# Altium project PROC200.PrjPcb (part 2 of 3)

## Sheet PROC200_MII0_PHY2.SchDoc
size 431 x 279 mm; SheetNumber: 11; SheetTotal: 18
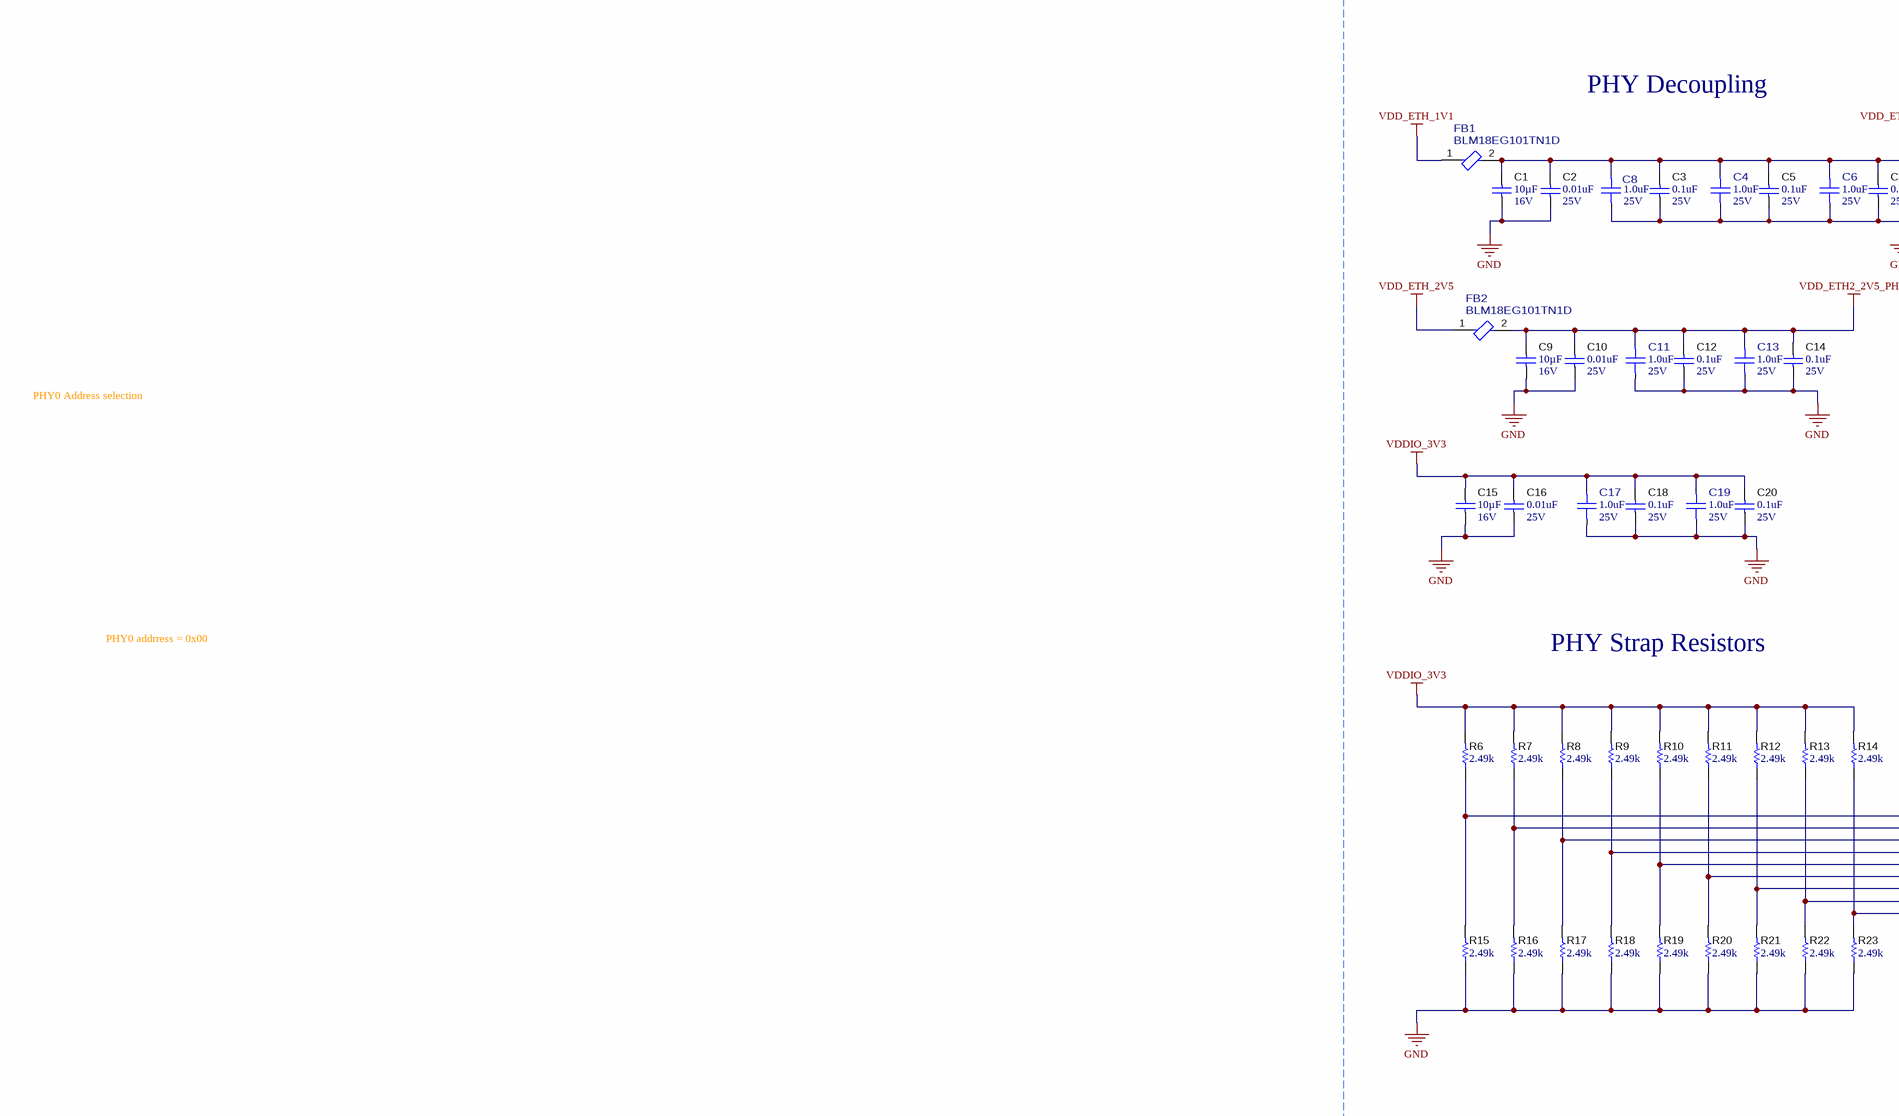
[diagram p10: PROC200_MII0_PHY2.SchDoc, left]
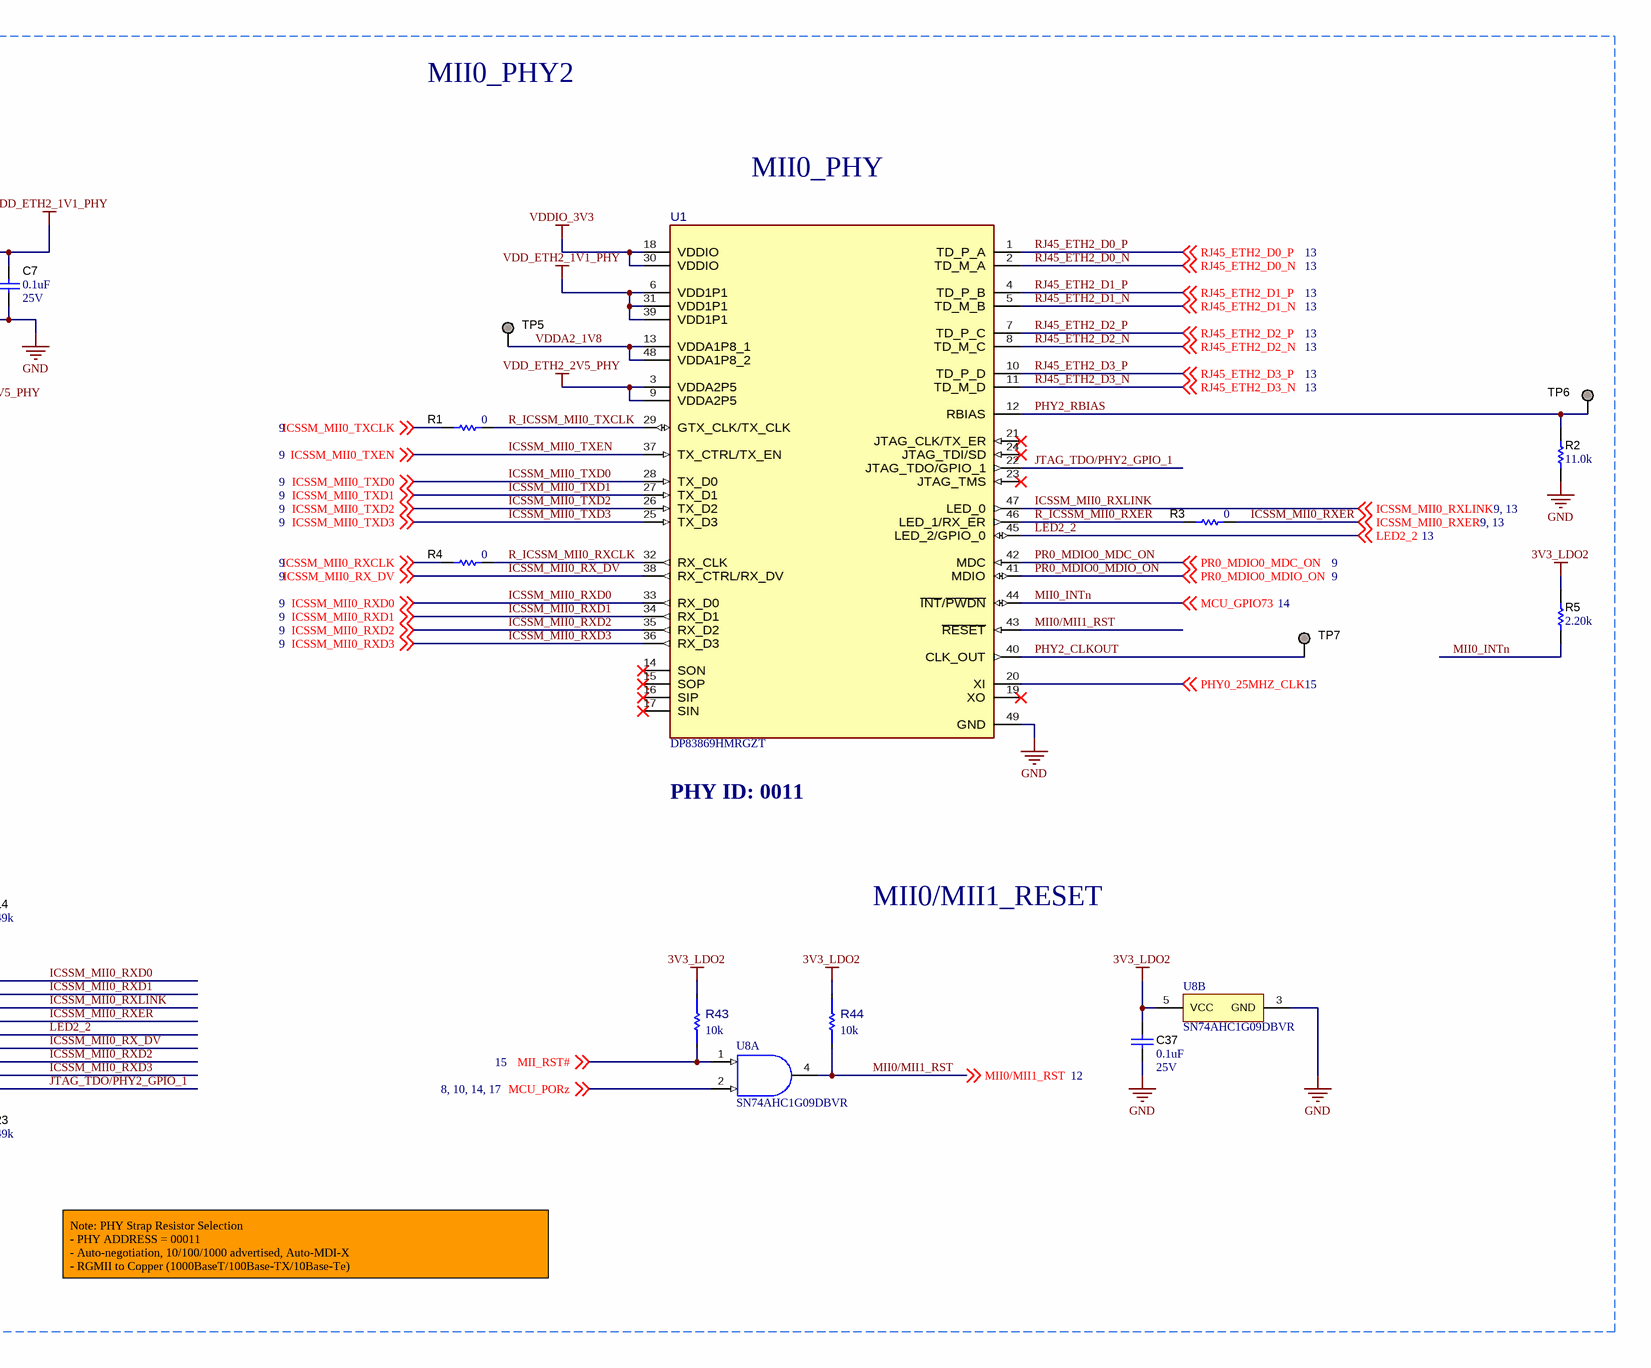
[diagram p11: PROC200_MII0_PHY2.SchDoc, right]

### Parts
C1  VDC_V: 16V  ValueDisplayed: 10µF  [0603]  (hidden comment: GRM188C81C106MA73D)
C2  Value2: 25V  ValueDisplayed: 0.01uF  [0402]  (hidden comment: GCM155R71E103KA37D)
C3  VDC_V: 25V  ValueDisplayed: 0.1uF  [0402]  (hidden comment: GRM155R71E104KE14D)
C4  ValueDisplayed: 1.0uF  VDC_V: 25V  [FP-GRM155C81E105KE11D_0402-MFG]  (hidden comment: GRM155C81E105KE11D)
C5  VDC_V: 25V  ValueDisplayed: 0.1uF  [0402]  (hidden comment: GRM155R71E104KE14D)
C6  ValueDisplayed: 1.0uF  VDC_V: 25V  [FP-GRM155C81E105KE11D_0402-MFG]  (hidden comment: GRM155C81E105KE11D)
C7  VDC_V: 25V  ValueDisplayed: 0.1uF  [0402]  (hidden comment: GRM155R71E104KE14D)
C8  ValueDisplayed: 1.0uF  VDC_V: 25V  [FP-GRM155C81E105KE11D_0402-MFG]  (hidden comment: GRM155C81E105KE11D)
C9  VDC_V: 16V  ValueDisplayed: 10µF  [0603]  (hidden comment: GRM188C81C106MA73D)
C10  Value2: 25V  ValueDisplayed: 0.01uF  [0402]  (hidden comment: GCM155R71E103KA37D)
C11  ValueDisplayed: 1.0uF  VDC_V: 25V  [FP-GRM155C81E105KE11D_0402-MFG]  (hidden comment: GRM155C81E105KE11D)
C12  VDC_V: 25V  ValueDisplayed: 0.1uF  [0402]  (hidden comment: GRM155R71E104KE14D)
C13  ValueDisplayed: 1.0uF  VDC_V: 25V  [FP-GRM155C81E105KE11D_0402-MFG]  (hidden comment: GRM155C81E105KE11D)
C14  VDC_V: 25V  ValueDisplayed: 0.1uF  [0402]  (hidden comment: GRM155R71E104KE14D)
C15  VDC_V: 16V  ValueDisplayed: 10µF  [0603]  (hidden comment: GRM188C81C106MA73D)
C16  Value2: 25V  ValueDisplayed: 0.01uF  [0402]  (hidden comment: GCM155R71E103KA37D)
C17  ValueDisplayed: 1.0uF  VDC_V: 25V  [FP-GRM155C81E105KE11D_0402-MFG]  (hidden comment: GRM155C81E105KE11D)
C18  VDC_V: 25V  ValueDisplayed: 0.1uF  [0402]  (hidden comment: GRM155R71E104KE14D)
C19  ValueDisplayed: 1.0uF  VDC_V: 25V  [FP-GRM155C81E105KE11D_0402-MFG]  (hidden comment: GRM155C81E105KE11D)
C20  VDC_V: 25V  ValueDisplayed: 0.1uF  [0402]  (hidden comment: GRM155R71E104KE14D)
C37  Value2: 25V  ValueDisplayed: 0.1uF  [0402]  (hidden comment: GRM155R71E104KE14D)
FB1  BLM18EG101TN1D  [FP-BLM18EG101TN1D_0603-MFG]
FB2  BLM18EG101TN1D  [FP-BLM18EG101TN1D_0603-MFG]
R1  ValueDisplayed: 0  [0402]  (hidden comment: ERJ-2GE0R00X)
R2  ValueDisplayed: 11.0k  [0402]  (hidden comment: CRCW040211K0FKED)
R3  ValueDisplayed: 0  [0402]  (hidden comment: ERJ-2GE0R00X)
R4  ValueDisplayed: 0  [0402]  (hidden comment: ERJ-2GE0R00X)
R5  ValueDisplayed: 2.20k  [0402]  (hidden comment: CRCW04022K20FKED)
R6  ValueDisplayed: 2.49k  [0402]  (hidden comment: CRCW04022K49FKED)
R7  ValueDisplayed: 2.49k  [0402]  (hidden comment: CRCW04022K49FKED)
R8  ValueDisplayed: 2.49k  [0402]  (hidden comment: CRCW04022K49FKED)
R9  ValueDisplayed: 2.49k  [0402]  (hidden comment: CRCW04022K49FKED)
R10  ValueDisplayed: 2.49k  [0402]  (hidden comment: CRCW04022K49FKED)
R11  ValueDisplayed: 2.49k  [0402]  (hidden comment: CRCW04022K49FKED)
R12  ValueDisplayed: 2.49k  [0402]  (hidden comment: CRCW04022K49FKED)
R13  ValueDisplayed: 2.49k  [0402]  (hidden comment: CRCW04022K49FKED)
R14  ValueDisplayed: 2.49k  [0402]  (hidden comment: CRCW04022K49FKED)
R15  ValueDisplayed: 2.49k  [0402]  (hidden comment: CRCW04022K49FKED)
R16  ValueDisplayed: 2.49k  [0402]  (hidden comment: CRCW04022K49FKED)
R17  ValueDisplayed: 2.49k  [0402]  (hidden comment: CRCW04022K49FKED)
R18  ValueDisplayed: 2.49k  [0402]  (hidden comment: CRCW04022K49FKED)
R19  ValueDisplayed: 2.49k  [0402]  (hidden comment: CRCW04022K49FKED)
R20  ValueDisplayed: 2.49k  [0402]  (hidden comment: CRCW04022K49FKED)
R21  ValueDisplayed: 2.49k  [0402]  (hidden comment: CRCW04022K49FKED)
R22  ValueDisplayed: 2.49k  [0402]  (hidden comment: CRCW04022K49FKED)
R23  ValueDisplayed: 2.49k  [0402]  (hidden comment: CRCW04022K49FKED)
R43  value 10k  [FP-RC0402JR-0710KL_0402-MFG]  (hidden comment: RC0402JR-0710KL)
R44  value 10k  [FP-RC0402JR-0710KL_0402-MFG]  (hidden comment: RC0402JR-0710KL)
TP5  TESTPOINT  [TP_25MIL-SMT]  (value not drawn)  (no BOM)
TP6  TESTPOINT  [TP_25MIL-SMT]  (value not drawn)  (no BOM)
TP7  TESTPOINT  [TP_25MIL-SMT]  (value not drawn)  (no BOM)
U1  DP83869HMRGZT  [RGZ0048B-MFG]
U8  SN74AHC1G09DBVR  [DBV0005A_N]  (parts A,B of 2)

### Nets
3V3_LDO2: C37.2 R5.2 R43.1 R44.1 U8.5(VCC)
GND: C1.1 C2.2 C3.2 C4.2 C5.2 C6.2 C7.2 C8.2 C9.1 C10.2 C11.2 C12.2 C13.2 C14.2 C15.1 C16.2 C17.2 C18.2 C19.2 C20.2 C37.1 R2.2 R15.1 R16.1 R17.1 R18.1 R19.1 R20.1 R21.1 R22.1 R23.1 U1.49(GND) U8.3(GND)
VDD_ETH2_1V1_PHY: C1.2 C2.1 C3.1 C4.1 C5.1 C6.1 C7.1 C8.1 FB1.2 U1.6(VDD1P1) U1.31(VDD1P1) U1.39(VDD1P1)
VDD_ETH2_2V5_PHY: C9.2 C10.1 C11.1 C12.1 C13.1 C14.1 FB2.2 U1.3(VDDA2P5) U1.9(VDDA2P5)
VDD_ETH_1V1: FB1.1
VDD_ETH_2V5: FB2.1
VDDIO_3V3: C15.2 C16.1 C17.1 C18.1 C19.1 C20.1 R6.2 R7.2 R8.2 R9.2 R10.2 R11.2 R12.2 R13.2 R14.2 U1.18(VDDIO) U1.30(VDDIO)
ICSSM_MII0_RX_DV: R11.1 R20.2 U1.38(RX_CTRL/RX_DV) ; off-sheet ICSSM_MII0_RX_DV
ICSSM_MII0_RXCLK: R4.1 ; off-sheet ICSSM_MII0_RXCLK
ICSSM_MII0_RXD0: R6.1 R15.2 U1.33(RX_D0) ; off-sheet ICSSM_MII0_RXD0
ICSSM_MII0_RXD1: R7.1 R16.2 U1.34(RX_D1) ; off-sheet ICSSM_MII0_RXD1
ICSSM_MII0_RXD2: R12.1 R21.2 U1.35(RX_D2) ; off-sheet ICSSM_MII0_RXD2
ICSSM_MII0_RXD3: R13.1 R22.2 U1.36(RX_D3) ; off-sheet ICSSM_MII0_RXD3
ICSSM_MII0_RXER: R3.2 R9.1 R18.2 ; off-sheet ICSSM_MII0_RXER
ICSSM_MII0_RXLINK: R8.1 R17.2 U1.47(LED_0) ; off-sheet ICSSM_MII0_RXLINK
ICSSM_MII0_TXCLK: R1.1 ; off-sheet ICSSM_MII0_TXCLK
ICSSM_MII0_TXD0: U1.28(TX_D0) ; off-sheet ICSSM_MII0_TXD0
ICSSM_MII0_TXD1: U1.27(TX_D1) ; off-sheet ICSSM_MII0_TXD1
ICSSM_MII0_TXD2: U1.26(TX_D2) ; off-sheet ICSSM_MII0_TXD2
ICSSM_MII0_TXD3: U1.25(TX_D3) ; off-sheet ICSSM_MII0_TXD3
ICSSM_MII0_TXEN: U1.37(TX_CTRL/TX_EN) ; off-sheet ICSSM_MII0_TXEN
JTAG_TDO/PHY2_GPIO_1: R14.1 R23.2 U1.22(JTAG_TDO/GPIO_1)
LED2_2: R10.1 R19.2 U1.45(LED_2/GPIO_0) ; off-sheet LED2_2
MCU_PORz: U8.2(B) ; off-sheet MCU_PORz
MII0/MII1_RST: R44.2 U1.43(~{RESET}) U8.4(Y) ; off-sheet MII0/MII1_RST
MII0_INTn: R5.1 U1.44(~{INT}/~{PWDN}) ; off-sheet MCU_GPIO73  [also labelled MCU_GPIO73]
MII_RST#: R43.2 U8.1(A) ; off-sheet MII_RST#
PHY0_25MHZ_CLK: U1.20(XI) ; off-sheet PHY0_25MHZ_CLK
PHY2_CLKOUT: TP7.1 U1.40(CLK_OUT)
PHY2_RBIAS: R2.1 TP6.1 U1.12(RBIAS)
PR0_MDIO0_MDC_ON: U1.42(MDC) ; off-sheet PR0_MDIO0_MDC_ON
PR0_MDIO0_MDIO_ON: U1.41(MDIO) ; off-sheet PR0_MDIO0_MDIO_ON
R_ICSSM_MII0_RXCLK: R4.2 U1.32(RX_CLK)
R_ICSSM_MII0_RXER: R3.1 U1.46(LED_1/RX_ER)
R_ICSSM_MII0_TXCLK: R1.2 U1.29(GTX_CLK/TX_CLK)
RJ45_ETH2_D0_N: U1.2(TD_M_A) ; off-sheet RJ45_ETH2_D0_N
RJ45_ETH2_D0_P: U1.1(TD_P_A) ; off-sheet RJ45_ETH2_D0_P
RJ45_ETH2_D1_N: U1.5(TD_M_B) ; off-sheet RJ45_ETH2_D1_N
RJ45_ETH2_D1_P: U1.4(TD_P_B) ; off-sheet RJ45_ETH2_D1_P
RJ45_ETH2_D2_N: U1.8(TD_M_C) ; off-sheet RJ45_ETH2_D2_N
RJ45_ETH2_D2_P: U1.7(TD_P_C) ; off-sheet RJ45_ETH2_D2_P
RJ45_ETH2_D3_N: U1.11(TD_M_D) ; off-sheet RJ45_ETH2_D3_N
RJ45_ETH2_D3_P: U1.10(TD_P_D) ; off-sheet RJ45_ETH2_D3_P
VDDA2_1V8: TP5.1 U1.13(VDDA1P8_1) U1.48(VDDA1P8_2)

Not connected (* = marked no-connect by the designer): U1 14(SON)* 15(SOP)* 16(SIP)* 17(SIN)* 19(XO)* 21(JTAG_CLK/TX_ER)* 23(JTAG_TMS)* 24(JTAG_TDI/SD)*

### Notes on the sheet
- MII0_PHY2
- PHY Decoupling
- MII0_PHY
- PHY0 Address selection
- PHY0 addrress = 0x00
- PHY Strap Resistors
- PHY ID: 0011
- MII0/MII1_RESET
- Note: PHY Strap Resistor Selection
  - PHY ADDRESS = 00011
  - Auto-negotiation, 10/100/1000 advertised, Auto-MDI-X
  - RGMII to Copper (1000BaseT/100Base-TX/10Base-Te)

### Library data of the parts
C1 C9 C15 = CMP-0086062-1: CAP, CERM, 10 µF, 16 V,+/- 20%, X6S, 0603; Manufacturer: MuRata; U/M: EA; AEC Category: Q200; SizeX_mm: 1.6; SizeY_mm: 0.8; SizeZ_mm: 1; Value: 10uF; SizeArea_mm2: 1.28; TaMin_C: -55°C; Polarized: N; SizeAreaWB_mm2: 4.68; TaMax_C: 105°C
C2 C10 C16 = CMP-0006352-2: CAP, CERM, 0.01 uF, 25 V, +/- 10%, X7R, 0402; Manufacturer: MuRata; TaMin_C: -55°C; Polarized: N; SizeAreaWB_mm2: 3; Value1: Unknown; U/M: EA; Value: 0.01uF; TaMax_C: 125°C; SizeZ_mm: 0.6; SizeX_mm: 1; SizeY_mm: 0.5; Cap_F: 10nF; AEC Category: Q200
C3 C5 C7 C12 C14 C18 C20 = CMP-0006659-2: CAP, CERM, 0.1 uF, 25 V, +/- 10%, X7R, 0402; Manufacturer: MuRata; TaMin_C: -55°C; Polarized: N; SizeAreaWB_mm2: 3; Value1: Unknown; U/M: EA; Value: 0.1uF; TaMax_C: 125°C; SizeZ_mm: 0.6; SizeX_mm: 1; SizeY_mm: 0.5; Cap_F: 100nF; AEC Category: Q200
C4 C6 C8 C11 C13 C17 C19 = CMP-0121658-2: Chip Multilayer Ceramic Capacitors for General Purpose, 0402, 1.0uF, X6S, 22%, 10%, 25V; Manufacturer: Murata; AEC Qualified: No; Cap_F: 1µF; SizeZ_mm: 0.6mm; Value: 1µF
C37 = CMP-0006659-2: CAP, CERM, 0.1 uF, 25 V, +/- 10%, X7R, 0402; Manufacturer: MuRata; TaMin_C: -55°C; Polarized: N; SizeAreaWB_mm2: 3; U/M: EA; Value: 0.1uF; TaMax_C: 125°C; SizeZ_mm: 0.6; SizeX_mm: 1; SizeY_mm: 0.5; Cap_F: 100nF; AEC Category: Q200; Value1: Unknown
FB1 FB2 = CMP-0122093-1: Chip Ferrite Bead, 0603, 100Ω @ 100MHz, 25%, 0.045Ω, 2A; Manufacturer: Murata; DCR_ohm: 45m; SizeZ_mm: 0.65mm; AEC Qualified: No
R1 R3 R4 = CMP-0026992-3: RES, 0, 5%, 0.1 W, AEC-Q200 Grade 0, 0402; Manufacturer: Panasonic; Power_W: 100mW; TempCo: 600 ppm/C; Value_Code: 0000; Value: 0; EIA_Code: E24; SizeX_mm: 1; SizeY_mm: 0.5; SizeZ_mm: 0.6; Value2: 0.1W; AEC Qualified: Y; VDC_V: 50V; AEC Category: Q200; SizeAreaWB_mm2: 3
R2 = CMP-0025975-3: RES, 11.0 k, 1%, 0.063 W, AEC-Q200 Grade 0, 0402; Manufacturer: Vishay-Dale; Power_W: 63mW; TempCo: 100 ppm/C; Value_Code: 11k0; Value: 11.0k; EIA_Code: E96; Res_ohm: 11k; SizeX_mm: 1; SizeY_mm: 0.5; SizeZ_mm: 0.6; Value2: 0.063W; AEC Qualified: Y; VDC_V: 50V; AEC Category: Q200; AEC Grade: 0
R5 = CMP-0026231-2: RES, 2.20 k, 1%, 0.063 W, AEC-Q200 Grade 0, 0402; Manufacturer: Vishay-Dale; Power_W: 63mW; TempCo: 100 ppm/C; Value_Code: 2k20; Value: 2.20k; Res_ohm: 2.2k; SizeX_mm: 1; SizeY_mm: 0.5; SizeZ_mm: 0.6; Value2: 0.063W; AEC Qualified: Y; AEC Category: Q200; AEC Grade: 0
R6-R23 = CMP-0026237-2: RES, 2.49 k, 1%, 0.063 W, AEC-Q200 Grade 0, 0402; Manufacturer: Vishay-Dale; Power_W: 63mW; TempCo: 100 ppm/C; Value_Code: 2k49; Value: 2.49k; EIA_Code: E96; SizeX_mm: 1; SizeY_mm: 0.5; SizeZ_mm: 0.6; Value2: 0.063W; AEC Qualified: Y; VDC_V: 50V; AEC Category: Q200; AEC Grade: 0
R43 R44 = CMP-0094798-1: Res Thick Film 0402 10K Ohm 5% 0.063W(1/16W) ±100ppm/C Pad SMD T/R; Manufacturer: YAGEO; AEC Qualified: No; Category Cd01000Bfc2916C6: Single Components; SizeZ_mm: 0.4mm; VDC_V: 50V; Category 5C6A91606D4187Ad: Resistors; TempCo: 100ppm/°C; Power_W: 63mW; Category 7542B8484461Ae85: Passive Components
TP5-TP7 = CMP-0078143-3: TEST POINT.  No entry in BOM.
U1 = CMP-0091377-1: 1/1 Transceiver Ethernet 48-VQFN (7x7); Manufacturer: Texas Instruments; TaMin_C: -40°C; SizeZ_mm: 1mm; TaMax_C: +125°C; Max Supply Voltage: 3.45V; Number Of Channels: 1; AEC Qualified: No; Data Rate: 1000Mbits/s; Min Supply Voltage: 990mV; Simplex Duplex: Full-Duplex; Standoff Height: 0mm
U8 = CMP-0051264-2: Single 2-Input Positive–AND Gate with Open Drain Output,  DBV0005A (SOT-23-5); Manufacturer: Texas Instruments; 3-State Output: No; Input Type: CMOS; Bits(#): 1; F @ Nom Voltage(Max)(Mhz): 75; tpd @ Nom Voltage(Max)(ns): 11,7.5; Voltage(Nom)(V): 3.3,5; Output Drive (IOL/IOH)(Max)(mA): 50/-50; Gate Type: AND; VCC(Max)(V): 5.5; ICC @ Nom Voltage(Max)(mA): 0.01; VCC(Min)(V): 2; Logic: True; Rating: Catalog; AEC Category: Q200; AEC Qualified: N; CompType: IC; SizeAreaWB_mm2: 14.82; SizeArea_mm2: 8.12; SizeX_mm: 2.8; SizeY_mm: 2.9; SizeZ_mm: 1.45

## Sheet PROC200_MII1_ADD_ON_CONN.SchDoc
size 431 x 279 mm; Date: Not shown in title block; ApprovedBy: Not shown in title block; CheckedBy: Not shown in title block; Author: Not shown in title block; CompanyName: Not shown in title block; Engineer: Not shown in title block; Organization: Not shown in title block; Address1: Not shown in title block; Address2: Not shown in title block; Address3: Not shown in title block; Address4: Not shown in title block; DocumentNumber: 5; Revision: Use project parameter SCH_Rev; SheetNumber: 12; SheetTotal: 18; PageSetup: Record=PageOptions¦CenterHorizontal=True¦CenterVertical=True¦PrintScale=1.00¦XCorrection=1.00¦YCorrection=1.00¦PrintKind=0¦BorderSize=5000000¦LeftOffset=0¦BottomOffset=0¦Orientation=2¦PaperLength=1000¦PaperWidth=1000¦Scale=100¦PaperSource=15¦PrintQuality=600¦MediaType=1¦DitherType=10¦PaperKind=Letter¦PrintScaleMode=1
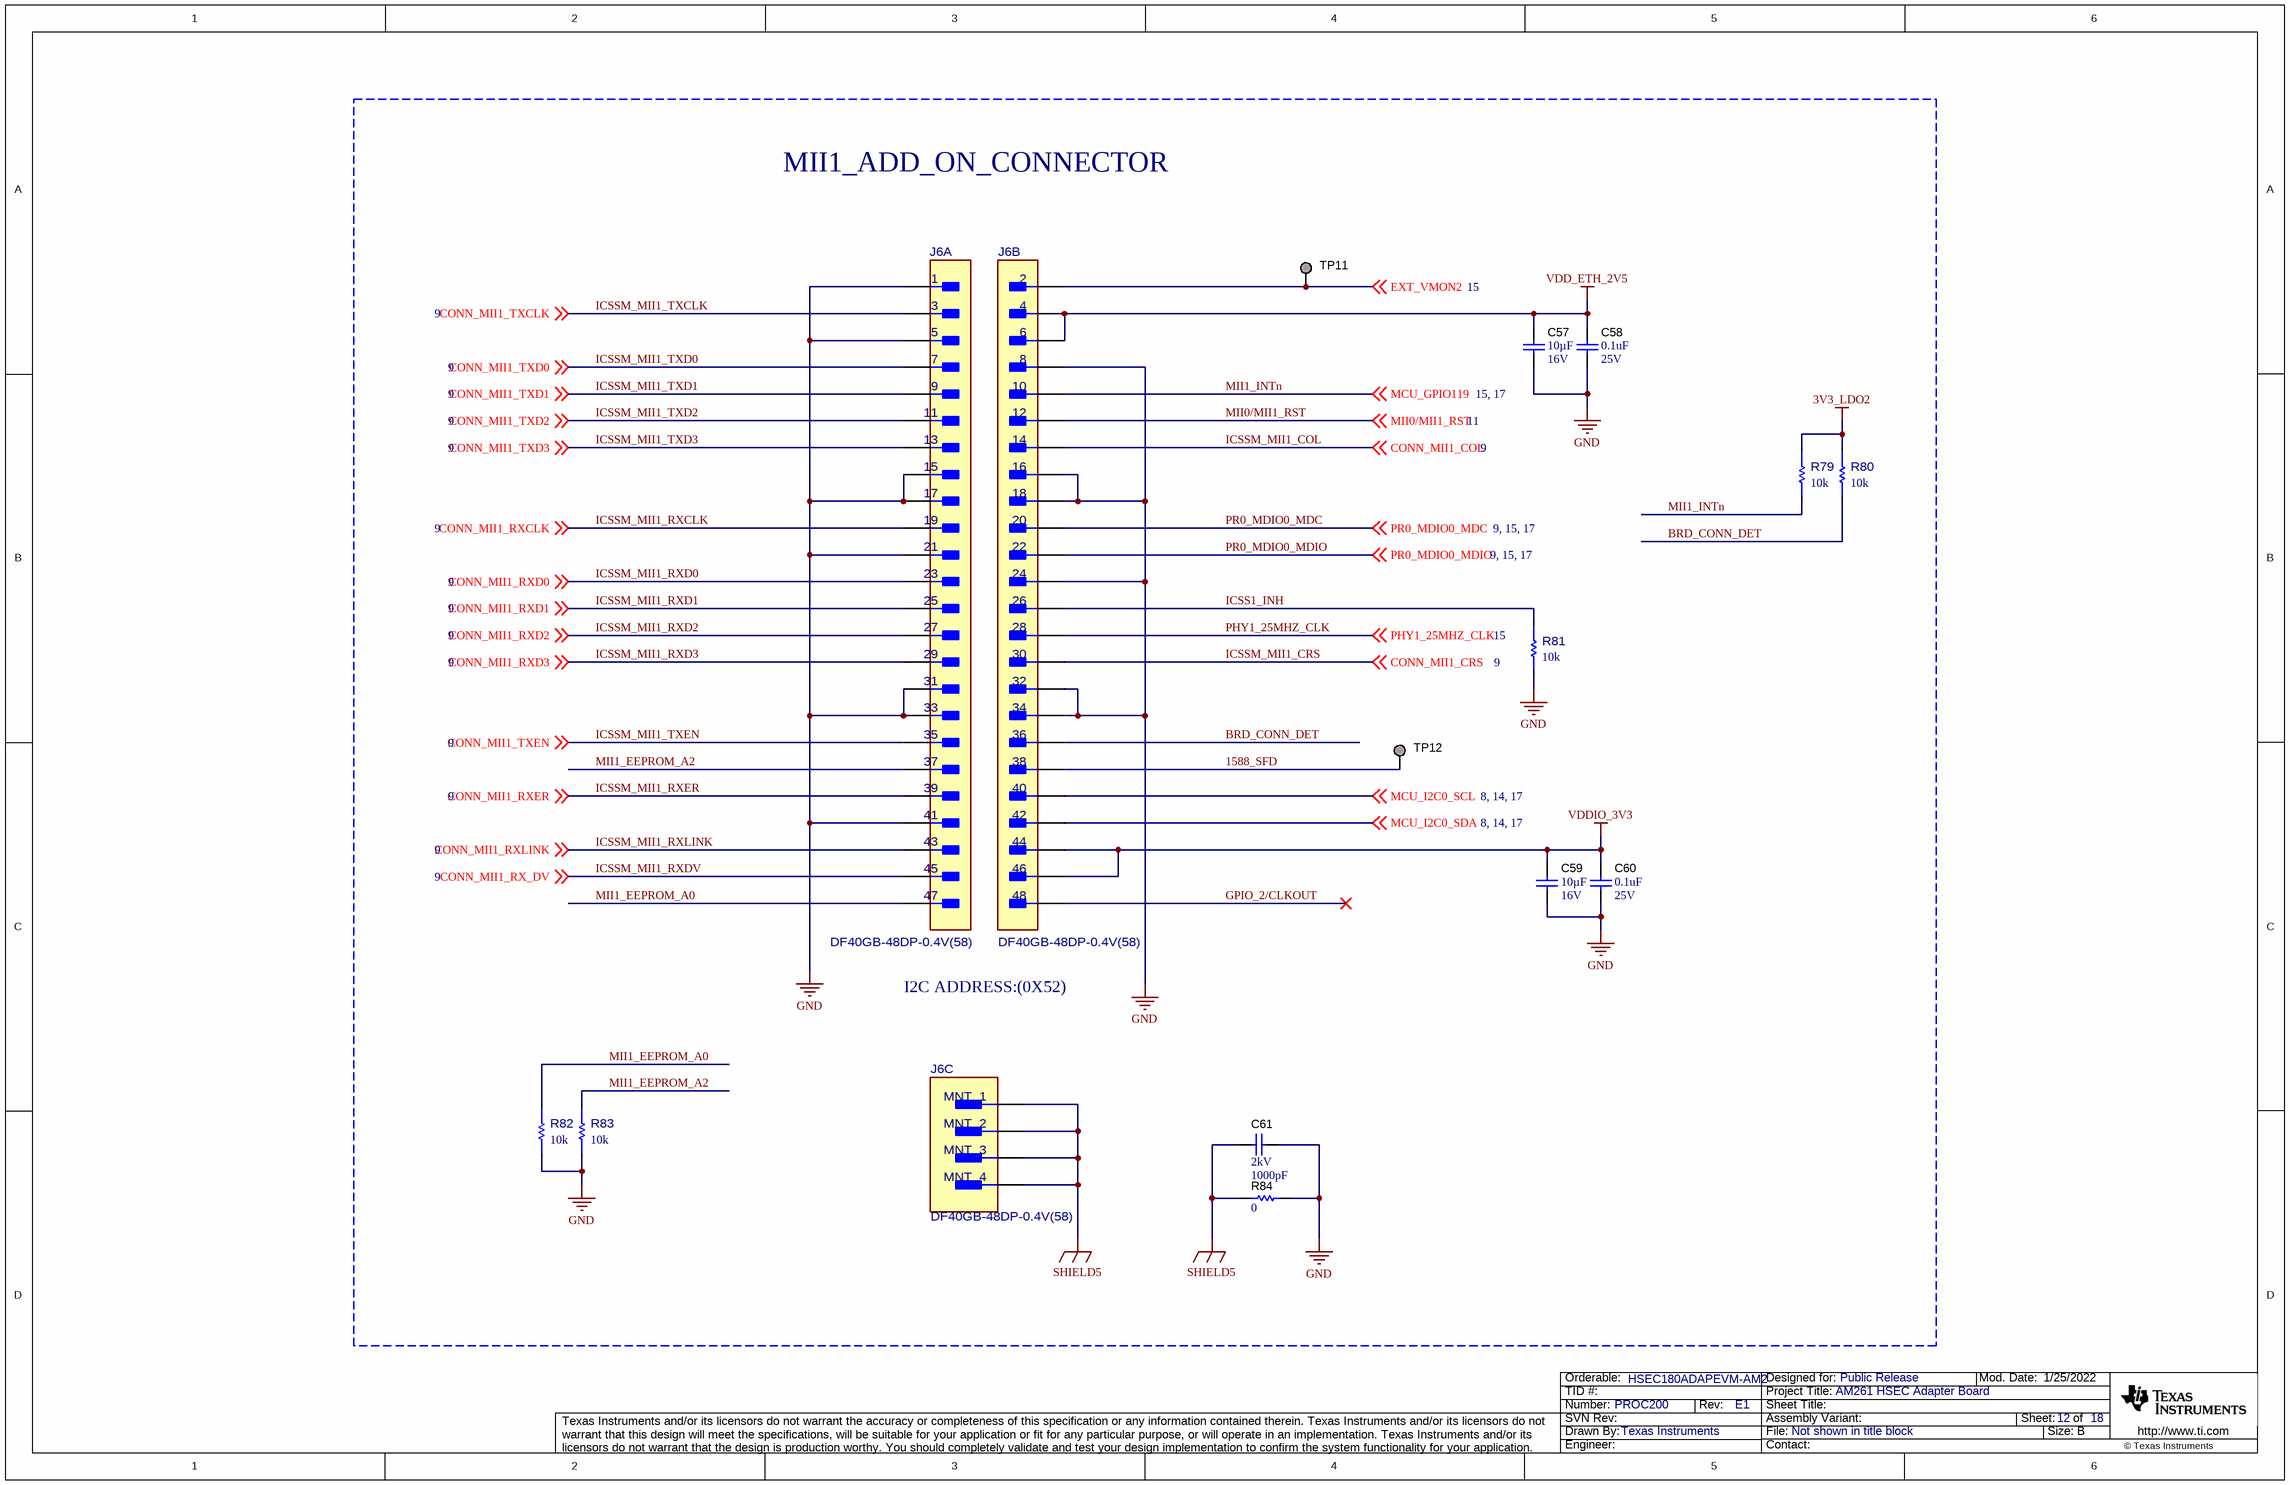
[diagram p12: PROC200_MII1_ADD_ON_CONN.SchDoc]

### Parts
C57  VDC_V: 16V  ValueDisplayed: 10µF  [0603]  (hidden comment: GRM188C81C106MA73D)
C58  VDC_V: 25V  ValueDisplayed: 0.1uF  [0402]  (hidden comment: GRM155R71E104KE14D)
C59  VDC_V: 16V  ValueDisplayed: 10µF  [0603]  (hidden comment: GRM188C81C106MA73D)
C60  VDC_V: 25V  ValueDisplayed: 0.1uF  [0402]  (hidden comment: GRM155R71E104KE14D)
C61  VDC_V: 2kV  ValueDisplayed: 1000pF  [1808]  (hidden comment: GR442QR73D102KW01L)
J6  DF40GB-48DP-0.4V(58)  [FP-DF40GB-48DP-0.4V(58)_HDR48-MFG]  (parts A,B,C of 3)
R79  value 10k  [FP-RC0402JR-0710KL_0402-MFG]  (hidden comment: RC0402JR-0710KL)
R80  value 10k  [FP-RC0402JR-0710KL_0402-MFG]  (hidden comment: RC0402JR-0710KL)
R81  value 10k  [FP-RC0402JR-0710KL_0402-MFG]  (hidden comment: RC0402JR-0710KL)
R82  value 10k  [FP-RC0402JR-0710KL_0402-MFG]  (hidden comment: RC0402JR-0710KL)
R83  value 10k  [FP-RC0402JR-0710KL_0402-MFG]  (hidden comment: RC0402JR-0710KL)
R84  ValueDisplayed: 0  [0805_HV]  (hidden comment: ERJ-6GEY0R00V)
TP11  TESTPOINT  [TP_25MIL-SMT]  (value not drawn)  (no BOM)
TP12  TESTPOINT  [TP_25MIL-SMT]  (value not drawn)  (no BOM)

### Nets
3V3_LDO2: R79.1 R80.1
GND: C57.1 C58.2 C59.1 C60.2 C61.1 J6.1 J6.5 J6.8 J6.15 J6.16 J6.17 J6.18 J6.21 J6.24 J6.31 J6.32 J6.33 J6.34 J6.41 R81.2 R82.2 R83.2 R84.2
SHIELD5: C61.2 J6.49(MNT_1) J6.50(MNT_2) J6.51(MNT_3) J6.52(MNT_4) R84.1
VDD_ETH_2V5: C57.2 C58.1 J6.4 J6.6
VDDIO_3V3: C59.2 C60.1 J6.44 J6.46
1588_SFD: J6.38 TP12.1
BRD_CONN_DET: J6.36 R80.2
EXT_VMON2: J6.2 TP11.1 ; off-sheet EXT_VMON2
GPIO_2/CLKOUT: J6.48
ICSS1_INH: J6.26 R81.1
ICSSM_MII1_COL: J6.14 ; off-sheet CONN_MII1_COL  [also labelled CONN_MII1_COL]
ICSSM_MII1_CRS: J6.30 ; off-sheet CONN_MII1_CRS  [also labelled CONN_MII1_CRS]
ICSSM_MII1_RXCLK: J6.19 ; off-sheet CONN_MII1_RXCLK  [also labelled CONN_MII1_RXCLK]
ICSSM_MII1_RXD0: J6.23 ; off-sheet CONN_MII1_RXD0  [also labelled CONN_MII1_RXD0]
ICSSM_MII1_RXD1: J6.25 ; off-sheet CONN_MII1_RXD1  [also labelled CONN_MII1_RXD1]
ICSSM_MII1_RXD2: J6.27 ; off-sheet CONN_MII1_RXD2  [also labelled CONN_MII1_RXD2]
ICSSM_MII1_RXD3: J6.29 ; off-sheet CONN_MII1_RXD3  [also labelled CONN_MII1_RXD3]
ICSSM_MII1_RXDV: J6.45 ; off-sheet CONN_MII1_RX_DV  [also labelled CONN_MII1_RX_DV]
ICSSM_MII1_RXER: J6.39 ; off-sheet CONN_MII1_RXER  [also labelled CONN_MII1_RXER]
ICSSM_MII1_RXLINK: J6.43 ; off-sheet CONN_MII1_RXLINK  [also labelled CONN_MII1_RXLINK]
ICSSM_MII1_TXCLK: J6.3 ; off-sheet CONN_MII1_TXCLK  [also labelled CONN_MII1_TXCLK]
ICSSM_MII1_TXD0: J6.7 ; off-sheet CONN_MII1_TXD0  [also labelled CONN_MII1_TXD0]
ICSSM_MII1_TXD1: J6.9 ; off-sheet CONN_MII1_TXD1  [also labelled CONN_MII1_TXD1]
ICSSM_MII1_TXD2: J6.11 ; off-sheet CONN_MII1_TXD2  [also labelled CONN_MII1_TXD2]
ICSSM_MII1_TXD3: J6.13 ; off-sheet CONN_MII1_TXD3  [also labelled CONN_MII1_TXD3]
ICSSM_MII1_TXEN: J6.35 ; off-sheet CONN_MII1_TXEN  [also labelled CONN_MII1_TXEN]
MCU_I2C0_SCL: J6.40 ; off-sheet MCU_I2C0_SCL
MCU_I2C0_SDA: J6.42 ; off-sheet MCU_I2C0_SDA
MII0/MII1_RST: J6.12 ; off-sheet MII0/MII1_RST
MII1_EEPROM_A0: J6.47 R82.1
MII1_EEPROM_A2: J6.37 R83.1
MII1_INTn: J6.10 R79.2 ; off-sheet MCU_GPIO119  [also labelled MCU_GPIO119]
PHY1_25MHZ_CLK: J6.28 ; off-sheet PHY1_25MHZ_CLK
PR0_MDIO0_MDC: J6.20 ; off-sheet PR0_MDIO0_MDC
PR0_MDIO0_MDIO: J6.22 ; off-sheet PR0_MDIO0_MDIO

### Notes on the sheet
- MII1_ADD_ON_CONNECTOR
- I2C ADDRESS:(0X52)

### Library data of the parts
C57 C59 = CMP-0086062-1: as C1 on sheet PROC200_MII0_PHY2
C58 C60 = CMP-0006659-2: as C3 on sheet PROC200_MII0_PHY2
C61 = CMP-0009436-2: CAP, CERM, 1000 pF, 2000 V, +/- 10%, X7R, 1808; Manufacturer: MuRata; TaMin_C: -55°C; Polarized: N; SizeAreaWB_mm2: 16.5; Value1: Unknown; U/M: EA; Value: 1000pF; TaMax_C: 125°C; SizeZ_mm: 2.03; SizeX_mm: 4.5; SizeY_mm: 2; Value2: 2000V; SizeArea_mm2: 9; Cap_F: 1nF; AEC Category: Q200
J6 = CMP-0121592-1: 48 Position Connector Plug, Outer Shroud Contacts Surface Mount Gold; Manufacturer: Hirose; ContactFinish: Gold,Nickel; Current_A: 300mA; Row_Count: 2; Voltage_V: 50V; AEC Qualified: No; Conn Gender: Male; Conn Orientation: Straight; DUT-Pitch_mm: 0.4mm; SizeZ_mm: 1.29mm
R79-R83 = CMP-0094798-1: as R43 on sheet PROC200_MII0_PHY2
R84 = CMP-0020616-3: RES, 0, 5%, 0.125 W, AEC-Q200 Grade 0, 0805; Manufacturer: Panasonic; Power_W: 125mW; TempCo: 600 ppm/C; Value_Code: 0000; Value: 0; EIA_Code: E24; SizeX_mm: 2; SizeY_mm: 1.25; SizeZ_mm: 1.45; Value2: 0.125W; SizeArea_mm2: 2.5; AEC Qualified: Y; VDC_V: 150V; AEC Category: Q200; SizeAreaWB_mm2: 6.75
TP11 TP12 = CMP-0078143-3: TEST POINT.  No entry in BOM.

## Sheet PROC200_RJ45_1_2.SchDoc
size 431 x 279 mm; Date: Not shown in title block; ApprovedBy: Not shown in title block; CheckedBy: Not shown in title block; Author: Not shown in title block; CompanyName: Not shown in title block; Engineer: Not shown in title block; Organization: Not shown in title block; Address1: Not shown in title block; Address2: Not shown in title block; Address3: Not shown in title block; Address4: Not shown in title block; DocumentNumber: 1; Revision: Use project parameter SCH_Rev; SheetNumber: 13; SheetTotal: 18; PageSetup: Record=PageOptions¦CenterHorizontal=True¦CenterVertical=True¦PrintScale=1.00¦XCorrection=1.00¦YCorrection=1.00¦PrintKind=0¦BorderSize=5000000¦LeftOffset=0¦BottomOffset=0¦Orientation=2¦PaperLength=1000¦PaperWidth=1000¦Scale=100¦PaperSource=15¦PrintQuality=600¦MediaType=1¦DitherType=10¦PaperKind=Letter¦PrintScaleMode=1
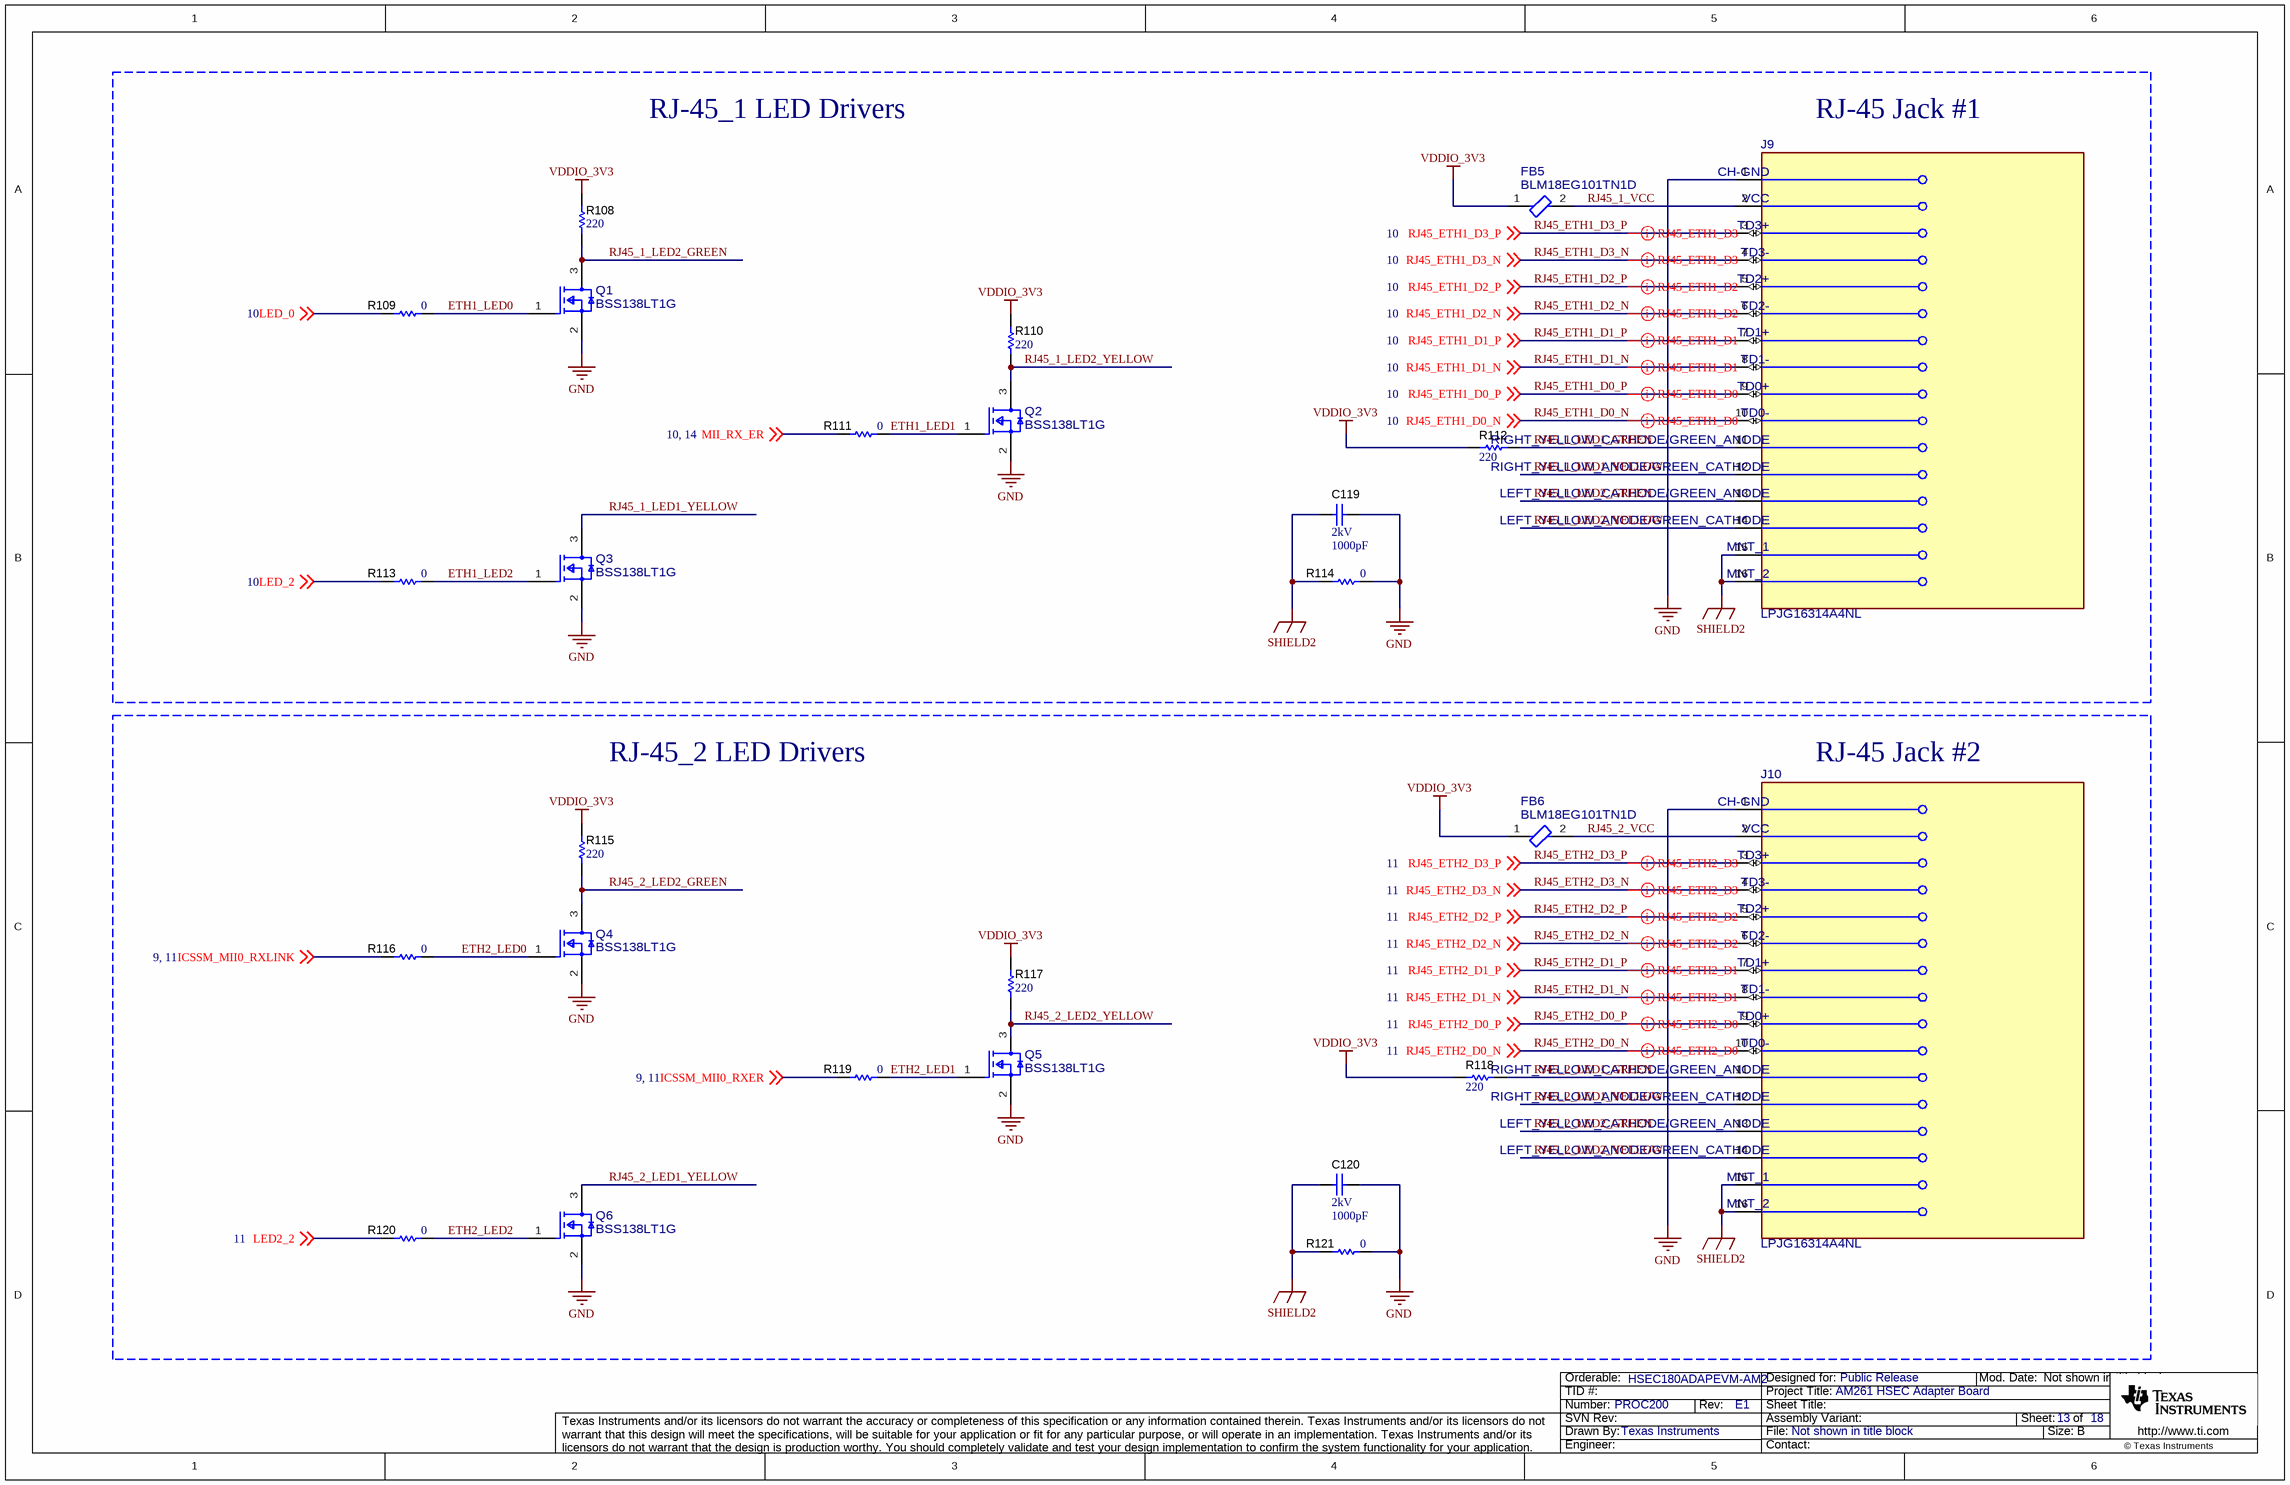
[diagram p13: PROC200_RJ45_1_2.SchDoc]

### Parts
C119  VDC_V: 2kV  ValueDisplayed: 1000pF  [1808]  (hidden comment: GR442QR73D102KW01L)
C120  VDC_V: 2kV  ValueDisplayed: 1000pF  [1808]  (hidden comment: GR442QR73D102KW01L)
FB5  BLM18EG101TN1D  [FP-BLM18EG101TN1D_0603-MFG]
FB6  BLM18EG101TN1D  [FP-BLM18EG101TN1D_0603-MFG]
J9  LPJG16314A4NL  [FP-LPJG16314A4NL_CONN_RJ45-MFG]
J10  LPJG16314A4NL  [FP-LPJG16314A4NL_CONN_RJ45-MFG]
Q1  BSS138LT1G  [FP-BSS138LT1G_SOT-23-3-MFG]
Q2  BSS138LT1G  [FP-BSS138LT1G_SOT-23-3-MFG]
Q3  BSS138LT1G  [FP-BSS138LT1G_SOT-23-3-MFG]
Q4  BSS138LT1G  [FP-BSS138LT1G_SOT-23-3-MFG]
Q5  BSS138LT1G  [FP-BSS138LT1G_SOT-23-3-MFG]
Q6  BSS138LT1G  [FP-BSS138LT1G_SOT-23-3-MFG]
R108  ValueDisplayed: 220  [0402]  (hidden comment: CRCW0402220RJNED)
R109  ValueDisplayed: 0  [0402]  (hidden comment: ERJ-2GE0R00X)
R110  ValueDisplayed: 220  [0402]  (hidden comment: CRCW0402220RJNED)
R111  ValueDisplayed: 0  [0402]  (hidden comment: ERJ-2GE0R00X)
R112  ValueDisplayed: 220  [0402]  (hidden comment: CRCW0402220RJNED)
R113  ValueDisplayed: 0  [0402]  (hidden comment: ERJ-2GE0R00X)
R114  ValueDisplayed: 0  [0805_HV]  (hidden comment: ERJ-6GEY0R00V)
R115  ValueDisplayed: 220  [0402]  (hidden comment: CRCW0402220RJNED)
R116  ValueDisplayed: 0  [0402]  (hidden comment: ERJ-2GE0R00X)
R117  ValueDisplayed: 220  [0402]  (hidden comment: CRCW0402220RJNED)
R118  ValueDisplayed: 220  [0402]  (hidden comment: CRCW0402220RJNED)
R119  ValueDisplayed: 0  [0402]  (hidden comment: ERJ-2GE0R00X)
R120  ValueDisplayed: 0  [0402]  (hidden comment: ERJ-2GE0R00X)
R121  ValueDisplayed: 0  [0805_HV]  (hidden comment: ERJ-6GEY0R00V)

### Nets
GND: C119.1 C120.1 J9.1(CH-GND) J10.1(CH-GND) Q1.2(S) Q2.2(S) Q3.2(S) Q4.2(S) Q5.2(S) Q6.2(S) R114.2 R121.2
SHIELD2: C119.2 C120.2 J9.15(MNT_1) J9.16(MNT_2) J10.15(MNT_1) J10.16(MNT_2) R114.1 R121.1
VDDIO_3V3: FB5.1 FB6.1 R108.2 R110.2 R112.1 R115.2 R117.2 R118.1
ETH1_LED0: Q1.1(G) R109.2
ETH1_LED1: Q2.1(G) R111.2
ETH1_LED2: Q3.1(G) R113.2
ETH2_LED0: Q4.1(G) R116.2
ETH2_LED1: Q5.1(G) R119.2
ETH2_LED2: Q6.1(G) R120.2
ICSSM_MII0_RXER: R119.1 ; off-sheet ICSSM_MII0_RXER
ICSSM_MII0_RXLINK: R116.1 ; off-sheet ICSSM_MII0_RXLINK
LED2_2: R120.1 ; off-sheet LED2_2
LED_0: R109.1 ; off-sheet LED_0
LED_2: R113.1 ; off-sheet LED_2
MII_RX_ER: R111.1 ; off-sheet MII_RX_ER
RJ45_1_LED1_GREEN: J9.11(RIGHT_YELLOW_CATHODE/GREEN_ANODE) R112.2
RJ45_1_LED1_YELLOW: J9.12(RIGHT_YELLOW_ANODE/GREEN_CATHODE) Q3.3(D)
RJ45_1_LED2_GREEN: J9.13(LEFT_YELLOW_CATHODE/GREEN_ANODE) Q1.3(D) R108.1
RJ45_1_LED2_YELLOW: J9.14(LEFT_YELLOW_ANODE/GREEN_CATHODE) Q2.3(D) R110.1
RJ45_1_VCC: FB5.2 J9.2(VCC)
RJ45_2_LED1_GREEN: J10.11(RIGHT_YELLOW_CATHODE/GREEN_ANODE) R118.2
RJ45_2_LED1_YELLOW: J10.12(RIGHT_YELLOW_ANODE/GREEN_CATHODE) Q6.3(D)
RJ45_2_LED2_GREEN: J10.13(LEFT_YELLOW_CATHODE/GREEN_ANODE) Q4.3(D) R115.1
RJ45_2_LED2_YELLOW: J10.14(LEFT_YELLOW_ANODE/GREEN_CATHODE) Q5.3(D) R117.1
RJ45_2_VCC: FB6.2 J10.2(VCC)
RJ45_ETH1_D0_N: J9.10(TD0-) ; off-sheet RJ45_ETH1_D0_N
RJ45_ETH1_D0_P: J9.9(TD0+) ; off-sheet RJ45_ETH1_D0_P
RJ45_ETH1_D1_N: J9.8(TD1-) ; off-sheet RJ45_ETH1_D1_N
RJ45_ETH1_D1_P: J9.7(TD1+) ; off-sheet RJ45_ETH1_D1_P
RJ45_ETH1_D2_N: J9.6(TD2-) ; off-sheet RJ45_ETH1_D2_N
RJ45_ETH1_D2_P: J9.5(TD2+) ; off-sheet RJ45_ETH1_D2_P
RJ45_ETH1_D3_N: J9.4(TD3-) ; off-sheet RJ45_ETH1_D3_N
RJ45_ETH1_D3_P: J9.3(TD3+) ; off-sheet RJ45_ETH1_D3_P
RJ45_ETH2_D0_N: J10.10(TD0-) ; off-sheet RJ45_ETH2_D0_N
RJ45_ETH2_D0_P: J10.9(TD0+) ; off-sheet RJ45_ETH2_D0_P
RJ45_ETH2_D1_N: J10.8(TD1-) ; off-sheet RJ45_ETH2_D1_N
RJ45_ETH2_D1_P: J10.7(TD1+) ; off-sheet RJ45_ETH2_D1_P
RJ45_ETH2_D2_N: J10.6(TD2-) ; off-sheet RJ45_ETH2_D2_N
RJ45_ETH2_D2_P: J10.5(TD2+) ; off-sheet RJ45_ETH2_D2_P
RJ45_ETH2_D3_N: J10.4(TD3-) ; off-sheet RJ45_ETH2_D3_N
RJ45_ETH2_D3_P: J10.3(TD3+) ; off-sheet RJ45_ETH2_D3_P

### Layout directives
differential pair; differential pair class RJ45_ETH1: RJ45_ETH1_D0_N, RJ45_ETH1_D0_P, RJ45_ETH1_D1_N, RJ45_ETH1_D1_P, RJ45_ETH1_D2_N, RJ45_ETH1_D2_P, RJ45_ETH1_D3_N, RJ45_ETH1_D3_P
differential pair; differential pair class RJ45_ETH2: RJ45_ETH2_D0_N, RJ45_ETH2_D0_P, RJ45_ETH2_D1_N, RJ45_ETH2_D1_P, RJ45_ETH2_D2_N, RJ45_ETH2_D2_P, RJ45_ETH2_D3_N, RJ45_ETH2_D3_P

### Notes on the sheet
- RJ-45_1 LED Drivers
- RJ-45 Jack #1
- RJ-45_2 LED Drivers
- RJ-45 Jack #2

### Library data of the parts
C119 C120 = CMP-0009436-2: as C61 on sheet PROC200_MII1_ADD_ON_CONN
FB5 FB6 = CMP-0122093-1: as FB1 on sheet PROC200_MII0_PHY2
J9 J10 = CMP-0093483-1: RJ45 Connector with 1000 Base-TX Inetgrated Magnetic; Manufacturer: Link-PP; SizeZ_mm: 13.7mm; AEC Qualified: No; DUT-Pitch_mm: 1.27mm; Conn Gender: Female; Is Female: yes; ContactFinish: Gold; Conn Orientation: Horizontal
Q1-Q6 = CMP-0122033-1: N-Channel 50 V 200mA (Ta) 225mW (Ta) Surface Mount SOT-23-3 (TO-236)D3-3; Manufacturer: On Semiconductor; AEC Qualified: No; Rdson45_ohm: 3.5; SizeZ_mm: 1.11mm; VdsMax_V: 50V; Vgs_V: 20V; ChMode: False; Ciiva Ids: 830104; Import Ts: 1521842931; Input Capacitace At Vds: 40pF @ 25V; Number Of Channels: 1; Pulse Drain Current: 800mA; Rthja Max: 556°C/W; Standoff Height: 0.01mm; Threshold Vgs Max: 1.5V; Threshold Vgs Min: 0.85V; TJmax_C: +150°C; Turn Off Delay Time: 20ns
R108 R110 R112 R115 R117 R118 = CMP-0026878-3: RES, 220, 5%, 0.063 W, AEC-Q200 Grade 0, 0402; Manufacturer: Vishay-Dale; Power_W: 63mW; TempCo: 200 ppm/C; Value_Code: 220R; Value: 220; EIA_Code: E24; SizeX_mm: 1; SizeY_mm: 0.5; SizeZ_mm: 0.6; Value2: 0.063W; AEC Qualified: Y; VDC_V: 50V; AEC Category: Q200; AEC Grade: 0
R109 R111 R113 R116 R119 R120 = CMP-0026992-3: as R1 on sheet PROC200_MII0_PHY2
R114 R121 = CMP-0020616-3: as R84 on sheet PROC200_MII1_ADD_ON_CONN

## Sheet PROC200_High_Density_conn1_2.SchDoc
size 431 x 279 mm; SheetNumber: 14; SheetTotal: 18
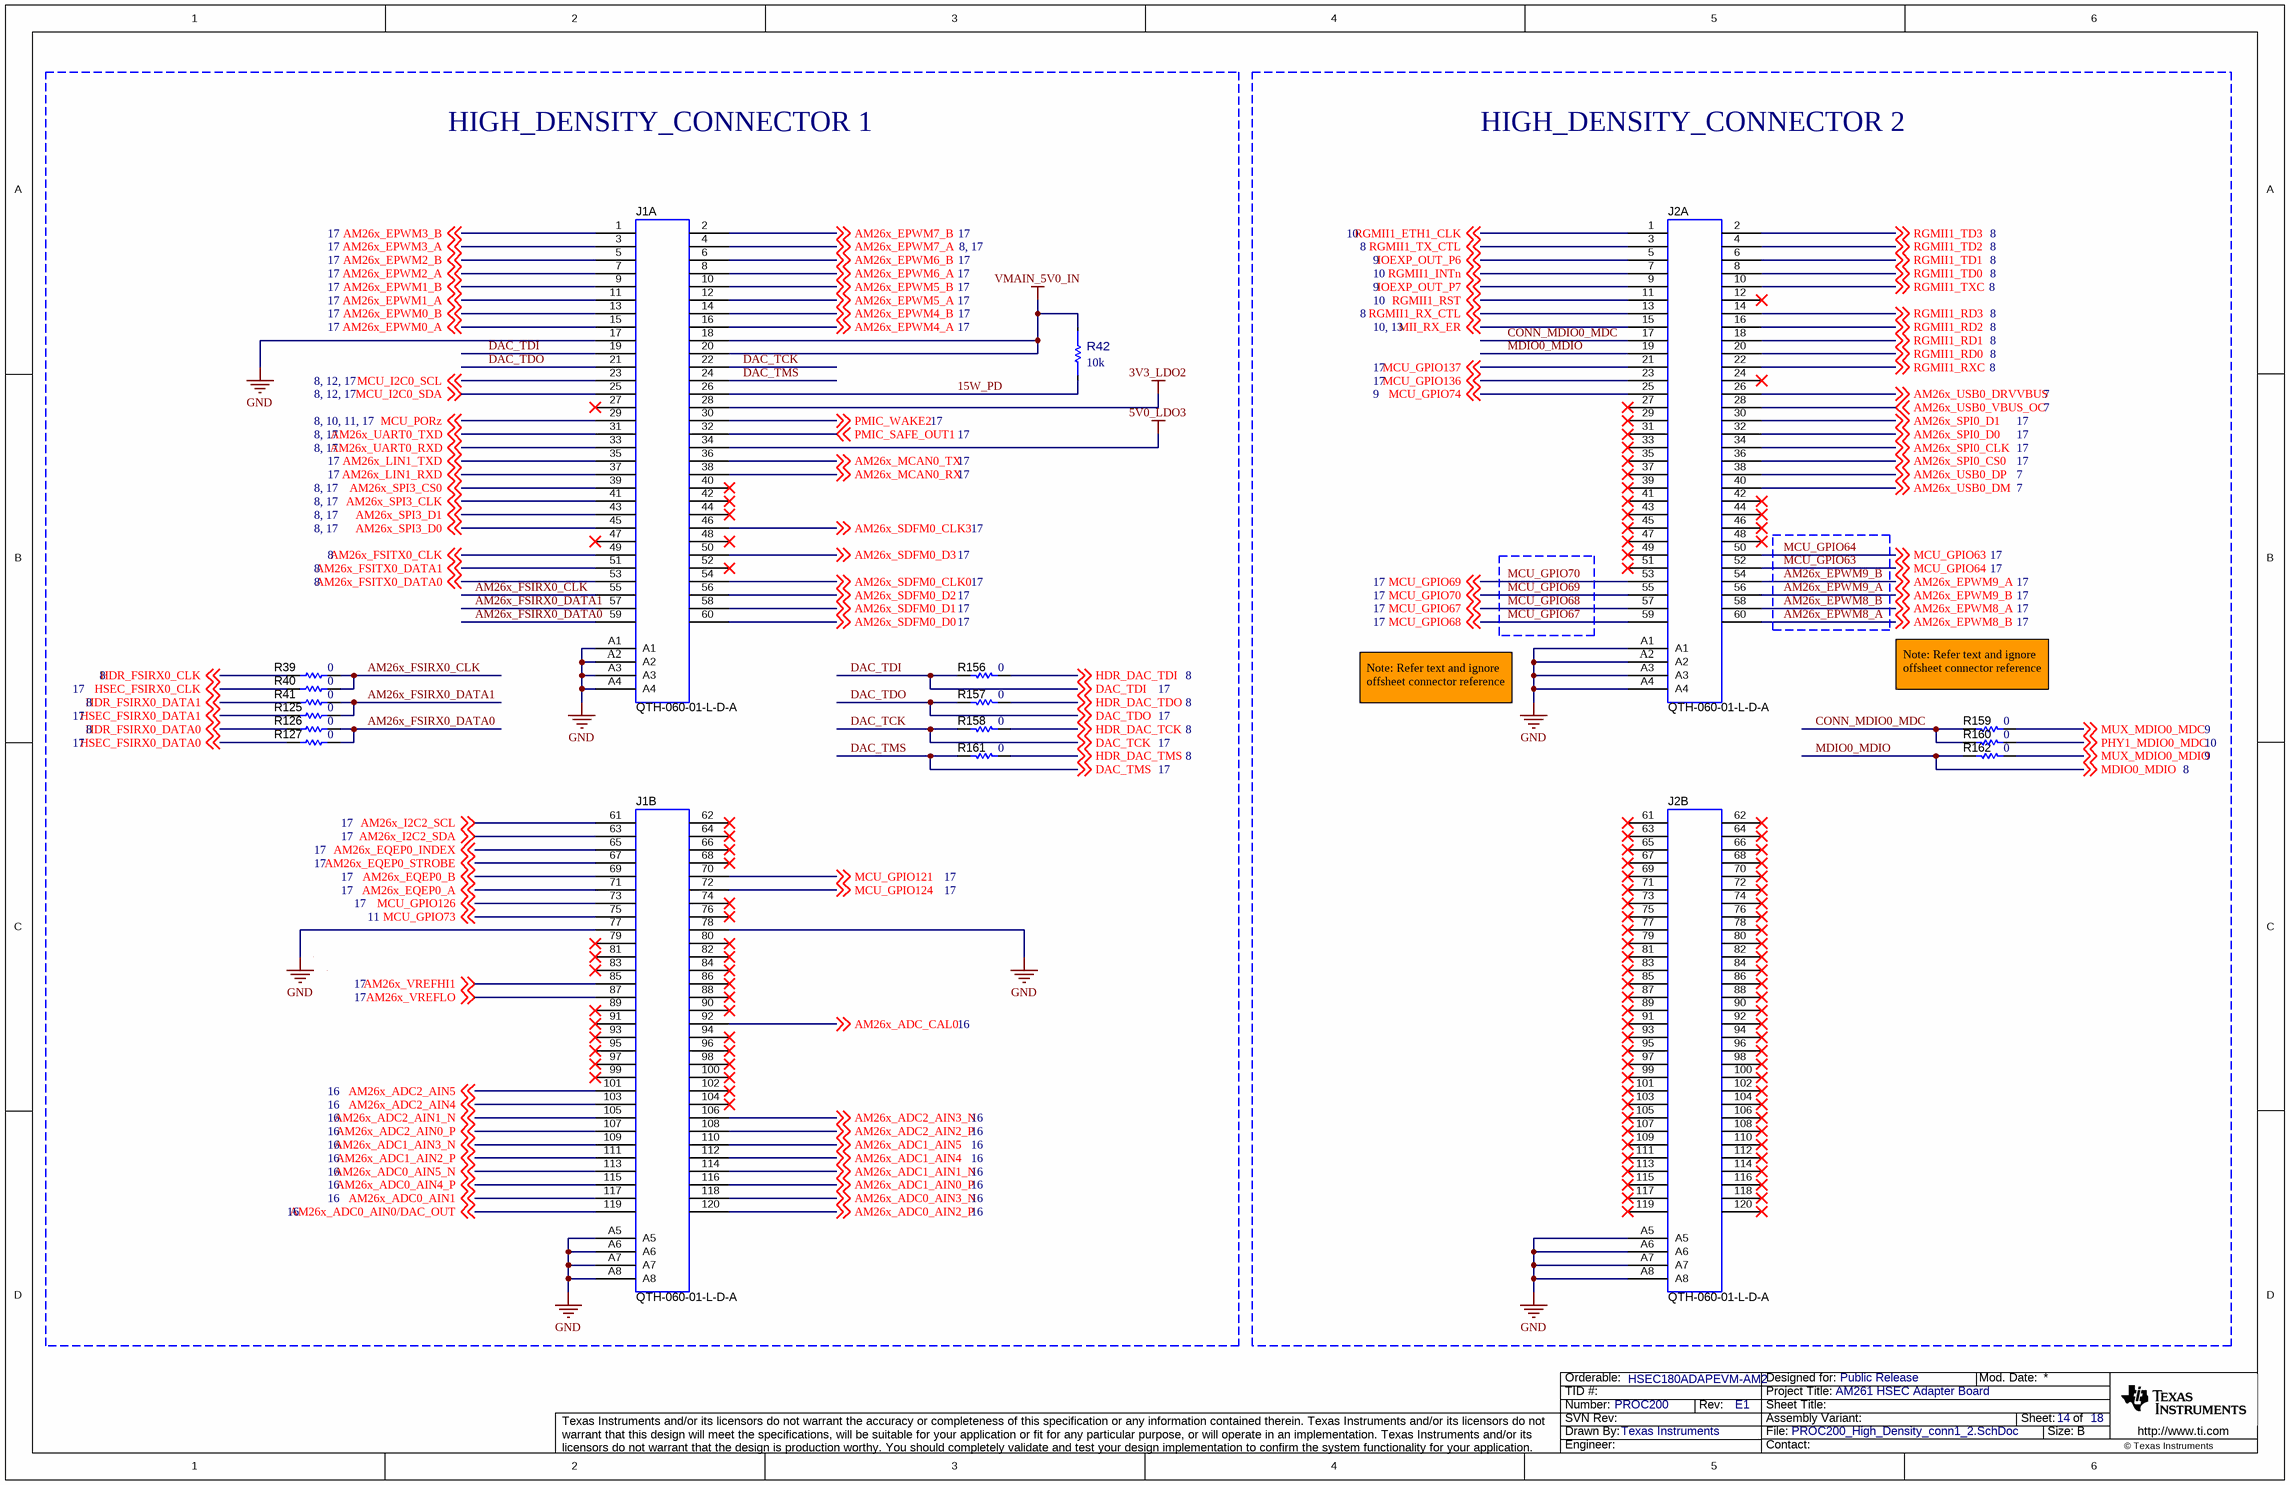
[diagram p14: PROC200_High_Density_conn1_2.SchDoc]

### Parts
J1  QTH-060-01-L-D-A  [SAMTEC_QTH-060-01-L-D-A]  (parts A,B of 2)
J2  QTH-060-01-L-D-A  [SAMTEC_QTH-060-01-L-D-A]  (parts A,B of 2)
R39  ValueDisplayed: 0  [0402]  (hidden comment: ERJ-2GE0R00X)
R40  ValueDisplayed: 0  [0402]  (hidden comment: ERJ-2GE0R00X)
R41  ValueDisplayed: 0  [0402]  (hidden comment: ERJ-2GE0R00X)
R42  value 10k  [FP-RC0402JR-0710KL_0402-MFG]  (hidden comment: RC0402JR-0710KL)
R125  ValueDisplayed: 0  [0402]  (hidden comment: ERJ-2GE0R00X)
R126  ValueDisplayed: 0  [0402]  (hidden comment: ERJ-2GE0R00X)
R127  ValueDisplayed: 0  [0402]  (hidden comment: ERJ-2GE0R00X)
R156  ValueDisplayed: 0  [0402]  (hidden comment: ERJ-2GE0R00X)
R157  ValueDisplayed: 0  [0402]  (hidden comment: ERJ-2GE0R00X)
R158  ValueDisplayed: 0  [0402]  (hidden comment: ERJ-2GE0R00X)
R159  ValueDisplayed: 0  [0402]  (hidden comment: ERJ-2GE0R00X)
R160  ValueDisplayed: 0  [0402]  (hidden comment: ERJ-2GE0R00X)
R161  ValueDisplayed: 0  [0402]  (hidden comment: ERJ-2GE0R00X)
R162  ValueDisplayed: 0  [0402]  (hidden comment: ERJ-2GE0R00X)

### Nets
3V3_LDO2: J1.28
5V0_LDO3: J1.34
GND: J1.17 J1.77 J1.78 J1.A1 J1.A2 J1.A3 J1.A4 J1.A5 J1.A6 J1.A7 J1.A8 J2.A1 J2.A2 J2.A3 J2.A4 J2.A5 J2.A6 J2.A7 J2.A8
VMAIN_5V0_IN: J1.18 J1.20 R42.1
15W_PD: J1.26 R42.2
AM26x_ADC0_AIN0/DAC_OUT: J1.119 ; off-sheet AM26x_ADC0_AIN0/DAC_OUT
AM26x_ADC0_AIN1: J1.117 ; off-sheet AM26x_ADC0_AIN1
AM26x_ADC0_AIN2_P: J1.120 ; off-sheet AM26x_ADC0_AIN2_P
AM26x_ADC0_AIN3_N: J1.118 ; off-sheet AM26x_ADC0_AIN3_N
AM26x_ADC0_AIN4_P: J1.115 ; off-sheet AM26x_ADC0_AIN4_P
AM26x_ADC0_AIN5_N: J1.113 ; off-sheet AM26x_ADC0_AIN5_N
AM26x_ADC1_AIN0_P: J1.116 ; off-sheet AM26x_ADC1_AIN0_P
AM26x_ADC1_AIN1_N: J1.114 ; off-sheet AM26x_ADC1_AIN1_N
AM26x_ADC1_AIN2_P: J1.111 ; off-sheet AM26x_ADC1_AIN2_P
AM26x_ADC1_AIN3_N: J1.109 ; off-sheet AM26x_ADC1_AIN3_N
AM26x_ADC1_AIN4: J1.112 ; off-sheet AM26x_ADC1_AIN4
AM26x_ADC1_AIN5: J1.110 ; off-sheet AM26x_ADC1_AIN5
AM26x_ADC2_AIN0_P: J1.107 ; off-sheet AM26x_ADC2_AIN0_P
AM26x_ADC2_AIN1_N: J1.105 ; off-sheet AM26x_ADC2_AIN1_N
AM26x_ADC2_AIN2_P: J1.108 ; off-sheet AM26x_ADC2_AIN2_P
AM26x_ADC2_AIN3_N: J1.106 ; off-sheet AM26x_ADC2_AIN3_N
AM26x_ADC2_AIN4: J1.103 ; off-sheet AM26x_ADC2_AIN4
AM26x_ADC2_AIN5: J1.101 ; off-sheet AM26x_ADC2_AIN5
AM26x_ADC_CAL0: J1.92 ; off-sheet AM26x_ADC_CAL0
AM26x_EPWM0_A: J1.15 ; off-sheet AM26x_EPWM0_A
AM26x_EPWM0_B: J1.13 ; off-sheet AM26x_EPWM0_B
AM26x_EPWM1_A: J1.11 ; off-sheet AM26x_EPWM1_A
AM26x_EPWM1_B: J1.9 ; off-sheet AM26x_EPWM1_B
AM26x_EPWM2_A: J1.7 ; off-sheet AM26x_EPWM2_A
AM26x_EPWM2_B: J1.5 ; off-sheet AM26x_EPWM2_B
AM26x_EPWM3_A: J1.3 ; off-sheet AM26x_EPWM3_A
AM26x_EPWM3_B: J1.1 ; off-sheet AM26x_EPWM3_B
AM26x_EPWM4_A: J1.16 ; off-sheet AM26x_EPWM4_A
AM26x_EPWM4_B: J1.14 ; off-sheet AM26x_EPWM4_B
AM26x_EPWM5_A: J1.12 ; off-sheet AM26x_EPWM5_A
AM26x_EPWM5_B: J1.10 ; off-sheet AM26x_EPWM5_B
AM26x_EPWM6_A: J1.8 ; off-sheet AM26x_EPWM6_A
AM26x_EPWM6_B: J1.6 ; off-sheet AM26x_EPWM6_B
AM26x_EPWM7_A: J1.4 ; off-sheet AM26x_EPWM7_A
AM26x_EPWM7_B: J1.2 ; off-sheet AM26x_EPWM7_B
AM26x_EPWM8_A: J2.58 ; off-sheet AM26x_EPWM8_A
AM26x_EPWM8_B: J2.60 ; off-sheet AM26x_EPWM8_B
AM26x_EPWM9_A: J2.54 ; off-sheet AM26x_EPWM9_A
AM26x_EPWM9_B: J2.56 ; off-sheet AM26x_EPWM9_B
AM26x_EQEP0_A: J1.71 ; off-sheet AM26x_EQEP0_A
AM26x_EQEP0_B: J1.69 ; off-sheet AM26x_EQEP0_B
AM26x_EQEP0_INDEX: J1.65 ; off-sheet AM26x_EQEP0_INDEX
AM26x_EQEP0_STROBE: J1.67 ; off-sheet AM26x_EQEP0_STROBE
AM26x_FSIRX0_CLK: J1.55 R39.2 R40.2
AM26x_FSIRX0_DATA0: J1.59 R126.2 R127.2
AM26x_FSIRX0_DATA1: J1.57 R41.2 R125.2
AM26x_FSITX0_CLK: J1.49 ; off-sheet AM26x_FSITX0_CLK
AM26x_FSITX0_DATA0: J1.53 ; off-sheet AM26x_FSITX0_DATA0
AM26x_FSITX0_DATA1: J1.51 ; off-sheet AM26x_FSITX0_DATA1
AM26x_I2C2_SCL: J1.61 ; off-sheet AM26x_I2C2_SCL
AM26x_I2C2_SDA: J1.63 ; off-sheet AM26x_I2C2_SDA
AM26x_LIN1_RXD: J1.37 ; off-sheet AM26x_LIN1_RXD
AM26x_LIN1_TXD: J1.35 ; off-sheet AM26x_LIN1_TXD
AM26x_MCAN0_RX: J1.38 ; off-sheet AM26x_MCAN0_RX
AM26x_MCAN0_TX: J1.36 ; off-sheet AM26x_MCAN0_TX
AM26x_SDFM0_CLK0: J1.54 ; off-sheet AM26x_SDFM0_CLK0
AM26x_SDFM0_CLK3: J1.46 ; off-sheet AM26x_SDFM0_CLK3
AM26x_SDFM0_D0: J1.60 ; off-sheet AM26x_SDFM0_D0
AM26x_SDFM0_D1: J1.58 ; off-sheet AM26x_SDFM0_D1
AM26x_SDFM0_D2: J1.56 ; off-sheet AM26x_SDFM0_D2
AM26x_SDFM0_D3: J1.50 ; off-sheet AM26x_SDFM0_D3
AM26x_SPI0_CLK: J2.34 ; off-sheet AM26x_SPI0_CLK
AM26x_SPI0_CS0: J2.36 ; off-sheet AM26x_SPI0_CS0
AM26x_SPI0_D0: J2.32 ; off-sheet AM26x_SPI0_D0
AM26x_SPI0_D1: J2.30 ; off-sheet AM26x_SPI0_D1
AM26x_SPI3_CLK: J1.41 ; off-sheet AM26x_SPI3_CLK
AM26x_SPI3_CS0: J1.39 ; off-sheet AM26x_SPI3_CS0
AM26x_SPI3_D0: J1.45 ; off-sheet AM26x_SPI3_D0
AM26x_SPI3_D1: J1.43 ; off-sheet AM26x_SPI3_D1
AM26x_UART0_RXD: J1.33 ; off-sheet AM26x_UART0_RXD
AM26x_UART0_TXD: J1.31 ; off-sheet AM26x_UART0_TXD
AM26x_USB0_DM: J2.40 ; off-sheet AM26x_USB0_DM
AM26x_USB0_DP: J2.38 ; off-sheet AM26x_USB0_DP
AM26x_USB0_DRVVBUS: J2.26 ; off-sheet AM26x_USB0_DRVVBUS
AM26x_USB0_VBUS_OC: J2.28 ; off-sheet AM26x_USB0_VBUS_OC  [project net USB0_VBUS_OC]
AM26x_VREFHI1: J1.85 ; off-sheet AM26x_VREFHI1
AM26x_VREFLO: J1.87 ; off-sheet AM26x_VREFLO
CONN_MDIO0_MDC: J2.17 R159.2 R160.2
DAC_TCK: J1.22 R158.2 ; off-sheet DAC_TCK
DAC_TDI: J1.19 R156.2 ; off-sheet DAC_TDI
DAC_TDO: J1.21 R157.2 ; off-sheet DAC_TDO
DAC_TMS: J1.24 R161.2 ; off-sheet DAC_TMS
HDR_DAC_TCK: R158.1 ; off-sheet HDR_DAC_TCK
HDR_DAC_TDI: R156.1 ; off-sheet HDR_DAC_TDI
HDR_DAC_TDO: R157.1 ; off-sheet HDR_DAC_TDO
HDR_DAC_TMS: R161.1 ; off-sheet HDR_DAC_TMS
HDR_FSIRX0_CLK: R39.1 ; off-sheet HDR_FSIRX0_CLK
HDR_FSIRX0_DATA0: R126.1 ; off-sheet HDR_FSIRX0_DATA0
HDR_FSIRX0_DATA1: R41.1 ; off-sheet HDR_FSIRX0_DATA1
HSEC_FSIRX0_CLK: R40.1 ; off-sheet HSEC_FSIRX0_CLK
HSEC_FSIRX0_DATA0: R127.1 ; off-sheet HSEC_FSIRX0_DATA0
HSEC_FSIRX0_DATA1: R125.1 ; off-sheet HSEC_FSIRX0_DATA1
IOEXP_OUT_P6: J2.5 ; off-sheet IOEXP_OUT_P6  [project net MII0_MUX_SEL]
IOEXP_OUT_P7: J2.9 ; off-sheet IOEXP_OUT_P7  [project net MII1_MUX_SEL]
MCU_GPIO63: J2.50 ; off-sheet MCU_GPIO63
MCU_GPIO64: J2.52 ; off-sheet MCU_GPIO64
MCU_GPIO67: J2.57 ; off-sheet MCU_GPIO67
MCU_GPIO68: J2.59 ; off-sheet MCU_GPIO68
MCU_GPIO69: J2.53 ; off-sheet MCU_GPIO69
MCU_GPIO70: J2.55 ; off-sheet MCU_GPIO70
MCU_GPIO73: J1.75 ; off-sheet MCU_GPIO73  [project net MII0_INTn]
MCU_GPIO74: J2.25 ; off-sheet MCU_GPIO74
MCU_GPIO121: J1.70 ; off-sheet MCU_GPIO121
MCU_GPIO124: J1.72 ; off-sheet MCU_GPIO124
MCU_GPIO126: J1.73 ; off-sheet MCU_GPIO126
MCU_GPIO136: J2.23 ; off-sheet MCU_GPIO136
MCU_GPIO137: J2.21 ; off-sheet MCU_GPIO137
MCU_I2C0_SCL: J1.23 ; off-sheet MCU_I2C0_SCL
MCU_I2C0_SDA: J1.25 ; off-sheet MCU_I2C0_SDA
MCU_PORz: J1.29 ; off-sheet MCU_PORz
MDIO0_MDIO: J2.19 R162.2 ; off-sheet MDIO0_MDIO
MII_RX_ER: J2.15 ; off-sheet MII_RX_ER
MUX_MDIO0_MDC: R159.1 ; off-sheet MUX_MDIO0_MDC
MUX_MDIO0_MDIO: R162.1 ; off-sheet MUX_MDIO0_MDIO
PHY1_MDIO0_MDC: R160.1 ; off-sheet PHY1_MDIO0_MDC
PMIC_SAFE_OUT1: J1.32 ; off-sheet PMIC_SAFE_OUT1
PMIC_WAKE2: J1.30 ; off-sheet PMIC_WAKE2
RGMII1_ETH1_CLK: J2.1 ; off-sheet RGMII1_ETH1_CLK
RGMII1_INTn: J2.7 ; off-sheet RGMII1_INTn
RGMII1_RD0: J2.20 ; off-sheet RGMII1_RD0
RGMII1_RD1: J2.18 ; off-sheet RGMII1_RD1
RGMII1_RD2: J2.16 ; off-sheet RGMII1_RD2
RGMII1_RD3: J2.14 ; off-sheet RGMII1_RD3
RGMII1_RST: J2.11 ; off-sheet RGMII1_RST
RGMII1_RX_CTL: J2.13 ; off-sheet RGMII1_RX_CTL
RGMII1_RXC: J2.22 ; off-sheet RGMII1_RXC
RGMII1_TD0: J2.8 ; off-sheet RGMII1_TD0
RGMII1_TD1: J2.6 ; off-sheet RGMII1_TD1
RGMII1_TD2: J2.4 ; off-sheet RGMII1_TD2
RGMII1_TD3: J2.2 ; off-sheet RGMII1_TD3
RGMII1_TX_CTL: J2.3 ; off-sheet RGMII1_TX_CTL
RGMII1_TXC: J2.10 ; off-sheet RGMII1_TXC

Not connected (* = marked no-connect by the designer): J1 27* 40* 42* 44* 47* 48* 52* 62* 64* 66* 68* 74* 76* 79* 80* 81* 82* 83* 84* 86* 88* 89* 90* 91* 93* 94* 95* 96* 97* 98* 99* 100* 102* 104*; J2 12* 24* 27* 29* 31* 33* 35* 37* 39* 41* 42* 43* 44* 45* 46* 47* 48* 49* 51* 61* 62* 63* 64* 65* 66* 67* 68* 69* 70* 71* 72* 73* 74* 75* 76* 77* 78* 79* 80* 81* 82* 83* 84* 85* 86* 87* 88* 89* 90* 91* 92* 93* 94* 95* 96* 97* 98* 99* 100* 101* 102* 103* 104* 105* 106* 107* 108* 109* 110* 111* 112* 113* 114* 115* 116* 117* 118* 119* 120*

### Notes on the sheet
- HIGH_DENSITY_CONNECTOR 1
- HIGH_DENSITY_CONNECTOR 2
- MCU_GPIO64
- MCU_GPIO63
- MCU_GPIO70
- MCU_GPIO69
- MCU_GPIO68
- MCU_GPIO67
- AM26x_EPWM9_B
- AM26x_EPWM9_A
- AM26x_EPWM8_B
- AM26x_EPWM8_A
- Note: Refer text and ignore offsheet connector reference

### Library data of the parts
J1 J2 = CMP-0056023-2: Socket, 0.5MM, 60x2, Gold, SMT; Manufacturer: Samtec; Green_Lifecycle: Not Set; Green_REACh: Incomplete
R39-R41 R125-R127 R156-R162 = CMP-0026992-3: as R1 on sheet PROC200_MII0_PHY2
R42 = CMP-0094798-1: as R43 on sheet PROC200_MII0_PHY2

## Sheet PROC200_High_Density_conn3.SchDoc
size 431 x 279 mm; SheetNumber: 15; SheetTotal: 18
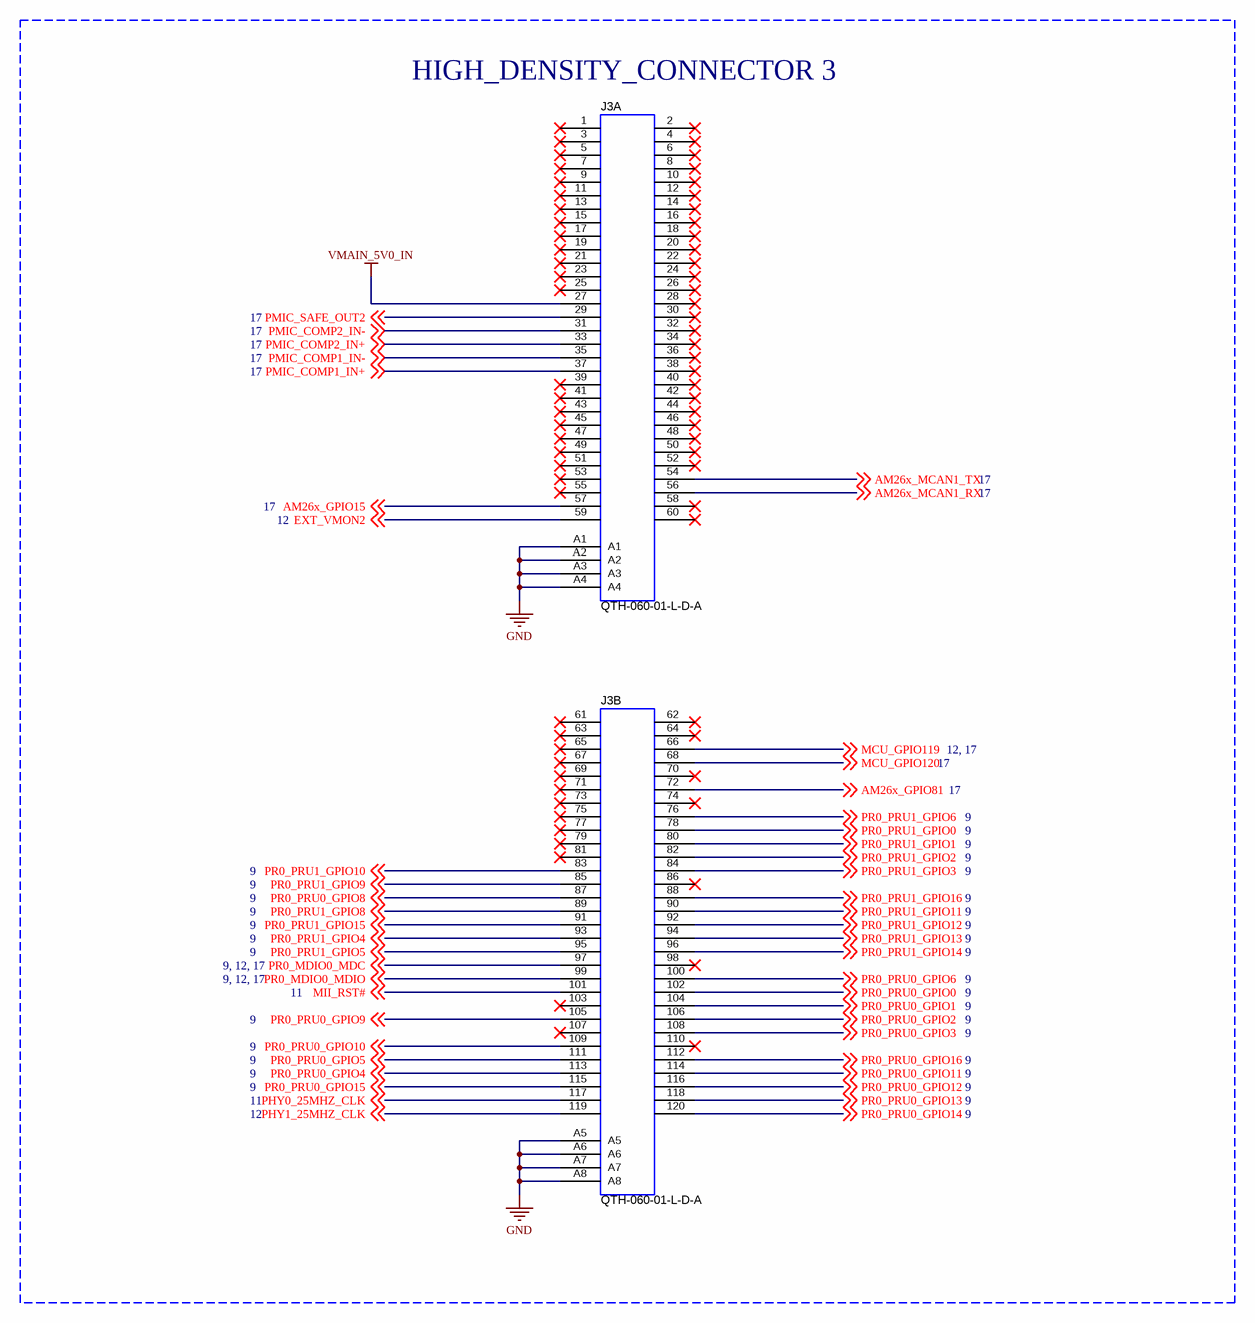
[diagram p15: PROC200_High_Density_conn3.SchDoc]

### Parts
J3  QTH-060-01-L-D-A  [SAMTEC_QTH-060-01-L-D-A]  (parts A,B of 2)

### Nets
GND: J3.A1 J3.A2 J3.A3 J3.A4 J3.A5 J3.A6 J3.A7 J3.A8
VMAIN_5V0_IN: J3.27
AM26x_GPIO15: J3.57 ; off-sheet AM26x_GPIO15
AM26x_GPIO81: J3.72 ; off-sheet AM26x_GPIO81
AM26x_MCAN1_RX: J3.56 ; off-sheet AM26x_MCAN1_RX
AM26x_MCAN1_TX: J3.54 ; off-sheet AM26x_MCAN1_TX
EXT_VMON2: J3.59 ; off-sheet EXT_VMON2
MCU_GPIO119: J3.66 ; off-sheet MCU_GPIO119  [project net MII1_INTn]
MCU_GPIO120: J3.68 ; off-sheet MCU_GPIO120
MII_RST#: J3.101 ; off-sheet MII_RST#
PHY0_25MHZ_CLK: J3.117 ; off-sheet PHY0_25MHZ_CLK
PHY1_25MHZ_CLK: J3.119 ; off-sheet PHY1_25MHZ_CLK
PMIC_COMP1_IN+: J3.37 ; off-sheet PMIC_COMP1_IN+
PMIC_COMP1_IN-: J3.35 ; off-sheet PMIC_COMP1_IN-
PMIC_COMP2_IN+: J3.33 ; off-sheet PMIC_COMP2_IN+
PMIC_COMP2_IN-: J3.31 ; off-sheet PMIC_COMP2_IN-
PMIC_SAFE_OUT2: J3.29 ; off-sheet PMIC_SAFE_OUT2
PR0_MDIO0_MDC: J3.97 ; off-sheet PR0_MDIO0_MDC
PR0_MDIO0_MDIO: J3.99 ; off-sheet PR0_MDIO0_MDIO
PR0_PRU0_GPIO0: J3.102 ; off-sheet PR0_PRU0_GPIO0
PR0_PRU0_GPIO1: J3.104 ; off-sheet PR0_PRU0_GPIO1
PR0_PRU0_GPIO2: J3.106 ; off-sheet PR0_PRU0_GPIO2
PR0_PRU0_GPIO3: J3.108 ; off-sheet PR0_PRU0_GPIO3
PR0_PRU0_GPIO4: J3.113 ; off-sheet PR0_PRU0_GPIO4
PR0_PRU0_GPIO5: J3.111 ; off-sheet PR0_PRU0_GPIO5
PR0_PRU0_GPIO6: J3.100 ; off-sheet PR0_PRU0_GPIO6
PR0_PRU0_GPIO8: J3.87 ; off-sheet PR0_PRU0_GPIO8
PR0_PRU0_GPIO9: J3.105 ; off-sheet PR0_PRU0_GPIO9
PR0_PRU0_GPIO10: J3.109 ; off-sheet PR0_PRU0_GPIO10
PR0_PRU0_GPIO11: J3.114 ; off-sheet PR0_PRU0_GPIO11
PR0_PRU0_GPIO12: J3.116 ; off-sheet PR0_PRU0_GPIO12
PR0_PRU0_GPIO13: J3.118 ; off-sheet PR0_PRU0_GPIO13
PR0_PRU0_GPIO14: J3.120 ; off-sheet PR0_PRU0_GPIO14
PR0_PRU0_GPIO15: J3.115 ; off-sheet PR0_PRU0_GPIO15
PR0_PRU0_GPIO16: J3.112 ; off-sheet PR0_PRU0_GPIO16
PR0_PRU1_GPIO0: J3.78 ; off-sheet PR0_PRU1_GPIO0
PR0_PRU1_GPIO1: J3.80 ; off-sheet PR0_PRU1_GPIO1
PR0_PRU1_GPIO2: J3.82 ; off-sheet PR0_PRU1_GPIO2
PR0_PRU1_GPIO3: J3.84 ; off-sheet PR0_PRU1_GPIO3
PR0_PRU1_GPIO4: J3.93 ; off-sheet PR0_PRU1_GPIO4
PR0_PRU1_GPIO5: J3.95 ; off-sheet PR0_PRU1_GPIO5
PR0_PRU1_GPIO6: J3.76 ; off-sheet PR0_PRU1_GPIO6
PR0_PRU1_GPIO8: J3.89 ; off-sheet PR0_PRU1_GPIO8
PR0_PRU1_GPIO9: J3.85 ; off-sheet PR0_PRU1_GPIO9
PR0_PRU1_GPIO10: J3.83 ; off-sheet PR0_PRU1_GPIO10
PR0_PRU1_GPIO11: J3.90 ; off-sheet PR0_PRU1_GPIO11
PR0_PRU1_GPIO12: J3.92 ; off-sheet PR0_PRU1_GPIO12
PR0_PRU1_GPIO13: J3.94 ; off-sheet PR0_PRU1_GPIO13
PR0_PRU1_GPIO14: J3.96 ; off-sheet PR0_PRU1_GPIO14
PR0_PRU1_GPIO15: J3.91 ; off-sheet PR0_PRU1_GPIO15
PR0_PRU1_GPIO16: J3.88 ; off-sheet PR0_PRU1_GPIO16

Not connected (* = marked no-connect by the designer): J3 1* 2* 3* 4* 5* 6* 7* 8* 9* 10* 11* 12* 13* 14* 15* 16* 17* 18* 19* 20* 21* 22* 23* 24* 25* 26* 28* 30* 32* 34* 36* 38* 39* 40* 41* 42* 43* 44* 45* 46* 47* 48* 49* 50* 51* 52* 53* 55* 58* 60* 61* 62* 63* 64* 65* 67* 69* 70* 71* 73* 74* 75* 77* 79* 81* 86* 98* 103* 107* 110*

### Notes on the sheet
- (near J3) HIGH_DENSITY_CONNECTOR 3

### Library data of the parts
J3 = CMP-0056023-2: as J1 on sheet PROC200_High_Density_conn1_2

## Sheet PROC200_HSEC_ADC.SchDoc
size 431 x 279 mm; SheetNumber: 16; SheetTotal: 18
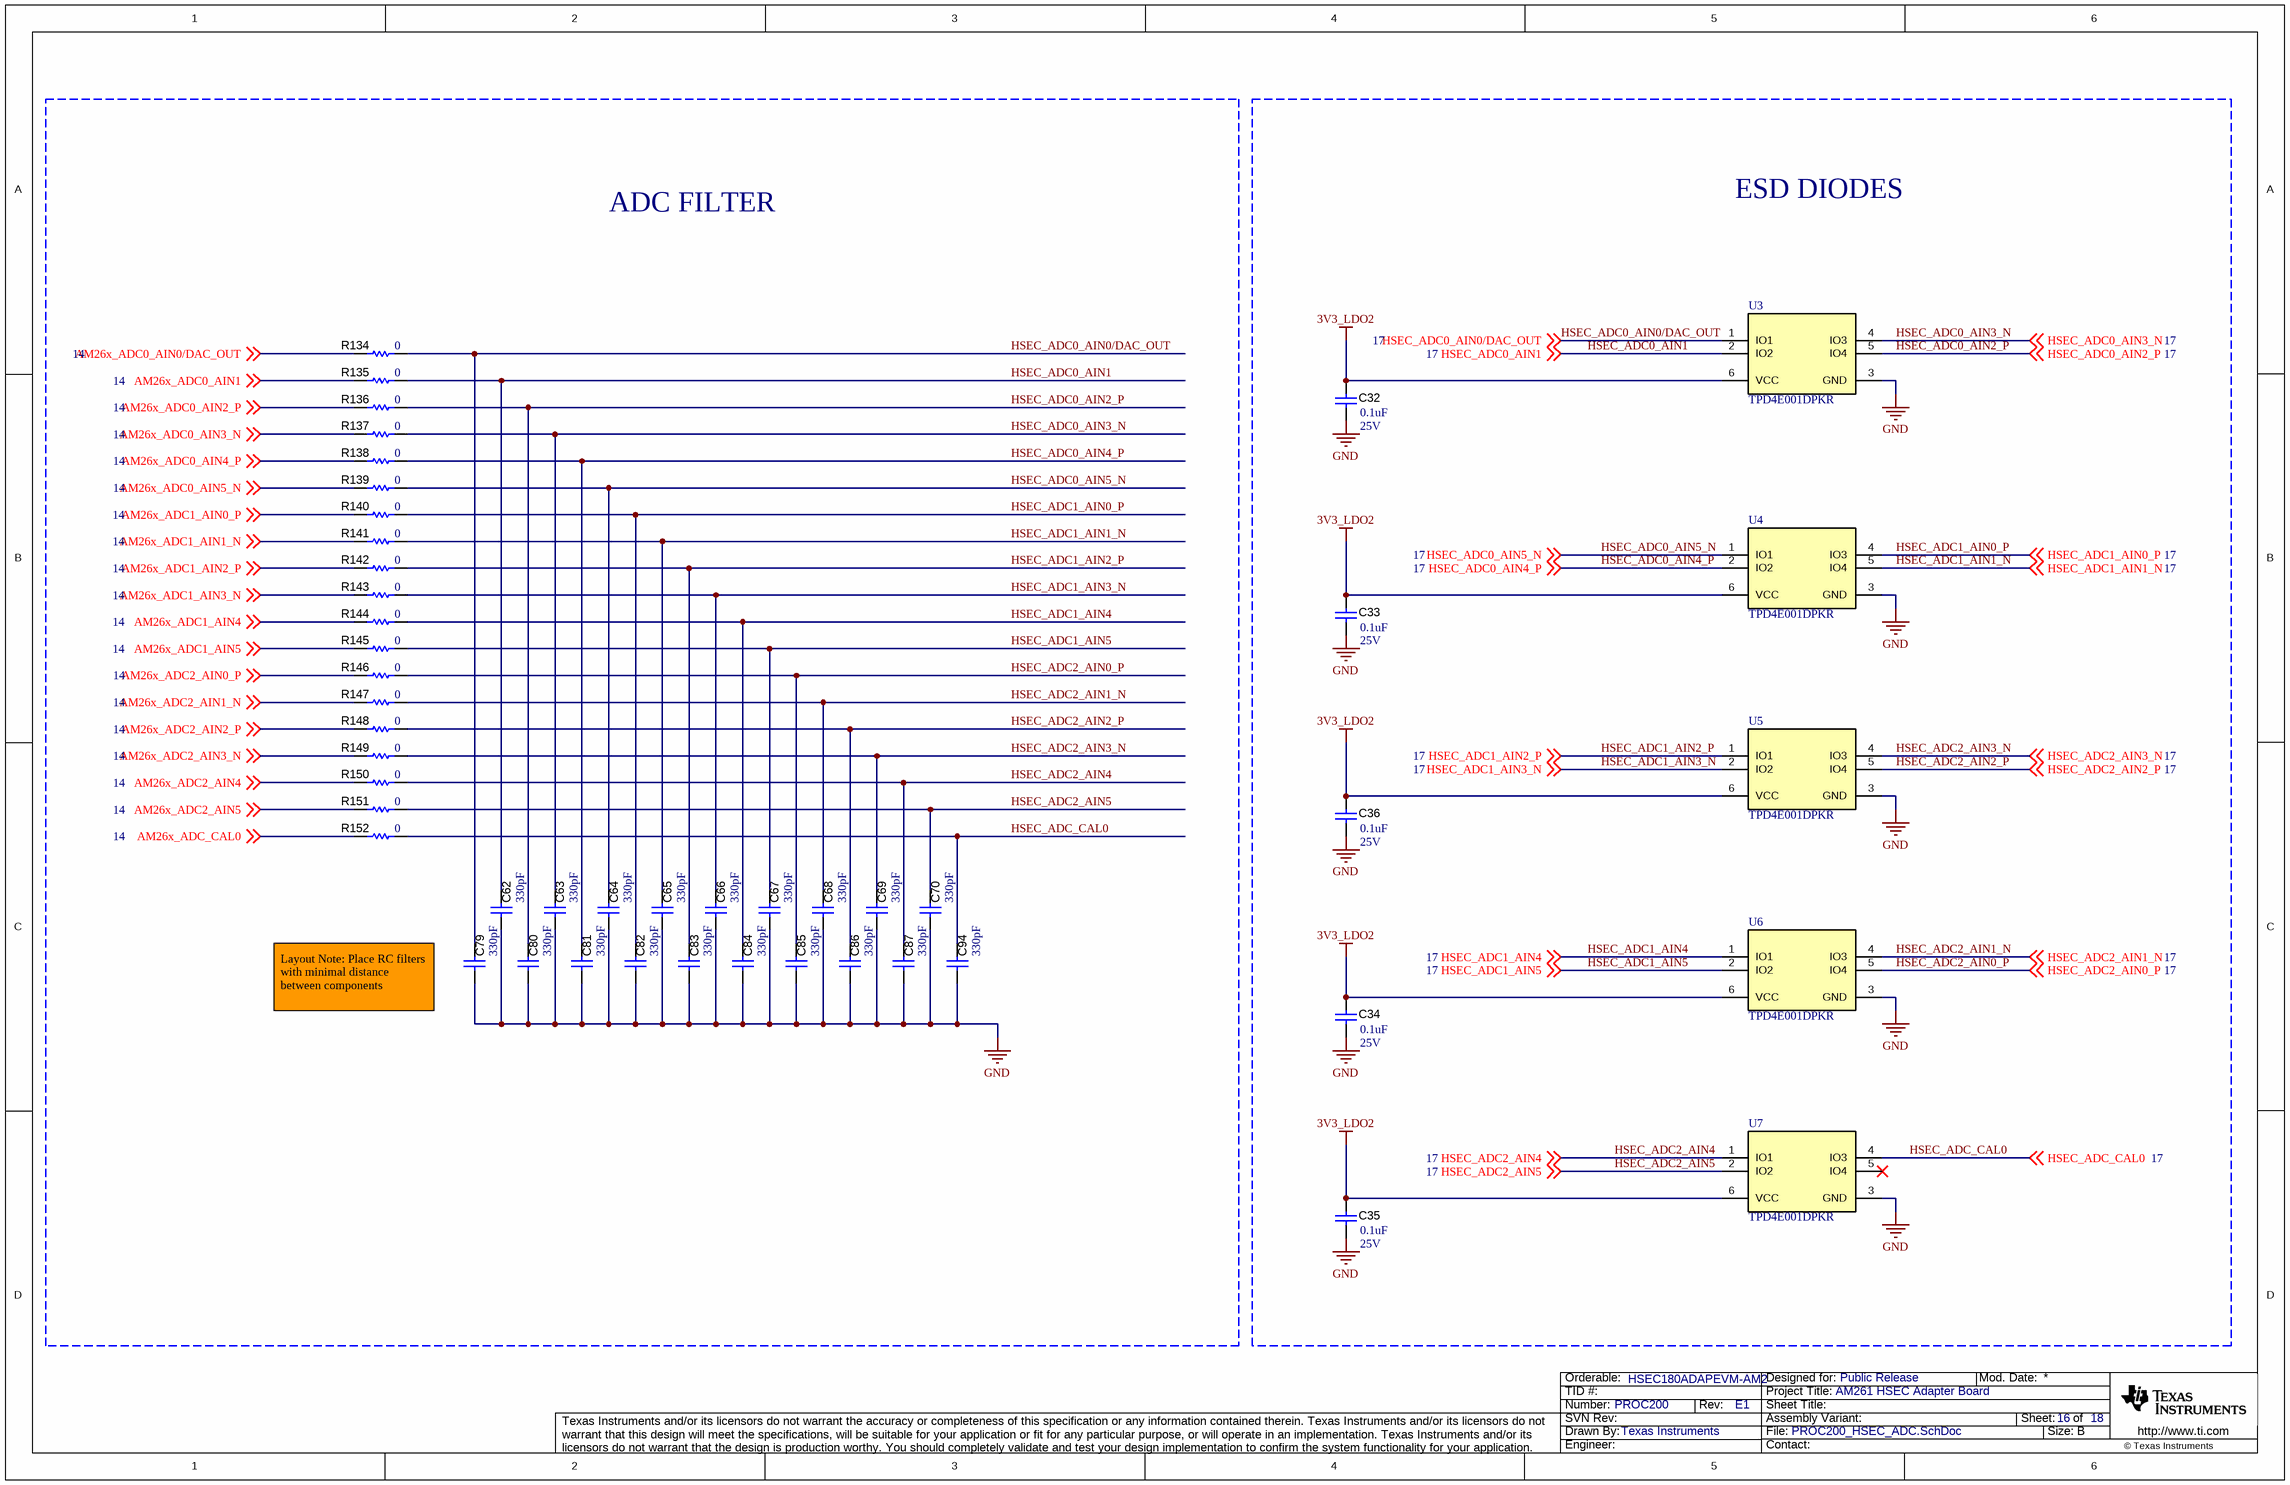
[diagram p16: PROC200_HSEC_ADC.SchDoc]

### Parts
C32  VDC_V: 25V  ValueDisplayed: 0.1uF  [0402]  (hidden comment: GRM155R71E104KE14D)
C33  VDC_V: 25V  ValueDisplayed: 0.1uF  [0402]  (hidden comment: GRM155R71E104KE14D)
C34  VDC_V: 25V  ValueDisplayed: 0.1uF  [0402]  (hidden comment: GRM155R71E104KE14D)
C35  VDC_V: 25V  ValueDisplayed: 0.1uF  [0402]  (hidden comment: GRM155R71E104KE14D)
C36  VDC_V: 25V  ValueDisplayed: 0.1uF  [0402]  (hidden comment: GRM155R71E104KE14D)
C62  ValueDisplayed: 330pF  [0402]  (hidden comment: GRM1555C1H331JA01D)
C63  ValueDisplayed: 330pF  [0402]  (hidden comment: GRM1555C1H331JA01D)
C64  ValueDisplayed: 330pF  [0402]  (hidden comment: GRM1555C1H331JA01D)
C65  ValueDisplayed: 330pF  [0402]  (hidden comment: GRM1555C1H331JA01D)
C66  ValueDisplayed: 330pF  [0402]  (hidden comment: GRM1555C1H331JA01D)
C67  ValueDisplayed: 330pF  [0402]  (hidden comment: GRM1555C1H331JA01D)
C68  ValueDisplayed: 330pF  [0402]  (hidden comment: GRM1555C1H331JA01D)
C69  ValueDisplayed: 330pF  [0402]  (hidden comment: GRM1555C1H331JA01D)
C70  ValueDisplayed: 330pF  [0402]  (hidden comment: GRM1555C1H331JA01D)
C79  ValueDisplayed: 330pF  [0402]  (hidden comment: GRM1555C1H331JA01D)
C80  ValueDisplayed: 330pF  [0402]  (hidden comment: GRM1555C1H331JA01D)
C81  ValueDisplayed: 330pF  [0402]  (hidden comment: GRM1555C1H331JA01D)
C82  ValueDisplayed: 330pF  [0402]  (hidden comment: GRM1555C1H331JA01D)
C83  ValueDisplayed: 330pF  [0402]  (hidden comment: GRM1555C1H331JA01D)
C84  ValueDisplayed: 330pF  [0402]  (hidden comment: GRM1555C1H331JA01D)
C85  ValueDisplayed: 330pF  [0402]  (hidden comment: GRM1555C1H331JA01D)
C86  ValueDisplayed: 330pF  [0402]  (hidden comment: GRM1555C1H331JA01D)
C87  ValueDisplayed: 330pF  [0402]  (hidden comment: GRM1555C1H331JA01D)
C94  ValueDisplayed: 330pF  [0402]  (hidden comment: GRM1555C1H331JA01D)
R134  ValueDisplayed: 0  [0402]  (hidden comment: ERJ-2GE0R00X)
R135  ValueDisplayed: 0  [0402]  (hidden comment: ERJ-2GE0R00X)
R136  ValueDisplayed: 0  [0402]  (hidden comment: ERJ-2GE0R00X)
R137  ValueDisplayed: 0  [0402]  (hidden comment: ERJ-2GE0R00X)
R138  ValueDisplayed: 0  [0402]  (hidden comment: ERJ-2GE0R00X)
R139  ValueDisplayed: 0  [0402]  (hidden comment: ERJ-2GE0R00X)
R140  ValueDisplayed: 0  [0402]  (hidden comment: ERJ-2GE0R00X)
R141  ValueDisplayed: 0  [0402]  (hidden comment: ERJ-2GE0R00X)
R142  ValueDisplayed: 0  [0402]  (hidden comment: ERJ-2GE0R00X)
R143  ValueDisplayed: 0  [0402]  (hidden comment: ERJ-2GE0R00X)
R144  ValueDisplayed: 0  [0402]  (hidden comment: ERJ-2GE0R00X)
R145  ValueDisplayed: 0  [0402]  (hidden comment: ERJ-2GE0R00X)
R146  ValueDisplayed: 0  [0402]  (hidden comment: ERJ-2GE0R00X)
R147  ValueDisplayed: 0  [0402]  (hidden comment: ERJ-2GE0R00X)
R148  ValueDisplayed: 0  [0402]  (hidden comment: ERJ-2GE0R00X)
R149  ValueDisplayed: 0  [0402]  (hidden comment: ERJ-2GE0R00X)
R150  ValueDisplayed: 0  [0402]  (hidden comment: ERJ-2GE0R00X)
R151  ValueDisplayed: 0  [0402]  (hidden comment: ERJ-2GE0R00X)
R152  ValueDisplayed: 0  [0402]  (hidden comment: ERJ-2GE0R00X)
U3  TPD4E001DPKR  [DPK0006A]
U4  TPD4E001DPKR  [DPK0006A]
U5  TPD4E001DPKR  [DPK0006A]
U6  TPD4E001DPKR  [DPK0006A]
U7  TPD4E001DPKR  [DPK0006A]

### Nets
3V3_LDO2: C32.1 C33.1 C34.1 C35.1 C36.1 U3.6(VCC) U4.6(VCC) U5.6(VCC) U6.6(VCC) U7.6(VCC)
GND: C32.2 C33.2 C34.2 C35.2 C36.2 C62.1 C63.1 C64.1 C65.1 C66.1 C67.1 C68.1 C69.1 C70.1 C79.1 C80.1 C81.1 C82.1 C83.1 C84.1 C85.1 C86.1 C87.1 C94.1 U3.3(GND) U4.3(GND) U5.3(GND) U6.3(GND) U7.3(GND)
AM26x_ADC0_AIN0/DAC_OUT: R134.1 ; off-sheet AM26x_ADC0_AIN0/DAC_OUT
AM26x_ADC0_AIN1: R135.1 ; off-sheet AM26x_ADC0_AIN1
AM26x_ADC0_AIN2_P: R136.1 ; off-sheet AM26x_ADC0_AIN2_P
AM26x_ADC0_AIN3_N: R137.1 ; off-sheet AM26x_ADC0_AIN3_N
AM26x_ADC0_AIN4_P: R138.1 ; off-sheet AM26x_ADC0_AIN4_P
AM26x_ADC0_AIN5_N: R139.1 ; off-sheet AM26x_ADC0_AIN5_N
AM26x_ADC1_AIN0_P: R140.1 ; off-sheet AM26x_ADC1_AIN0_P
AM26x_ADC1_AIN1_N: R141.1 ; off-sheet AM26x_ADC1_AIN1_N
AM26x_ADC1_AIN2_P: R142.1 ; off-sheet AM26x_ADC1_AIN2_P
AM26x_ADC1_AIN3_N: R143.1 ; off-sheet AM26x_ADC1_AIN3_N
AM26x_ADC1_AIN4: R144.1 ; off-sheet AM26x_ADC1_AIN4
AM26x_ADC1_AIN5: R145.1 ; off-sheet AM26x_ADC1_AIN5
AM26x_ADC2_AIN0_P: R146.1 ; off-sheet AM26x_ADC2_AIN0_P
AM26x_ADC2_AIN1_N: R147.1 ; off-sheet AM26x_ADC2_AIN1_N
AM26x_ADC2_AIN2_P: R148.1 ; off-sheet AM26x_ADC2_AIN2_P
AM26x_ADC2_AIN3_N: R149.1 ; off-sheet AM26x_ADC2_AIN3_N
AM26x_ADC2_AIN4: R150.1 ; off-sheet AM26x_ADC2_AIN4
AM26x_ADC2_AIN5: R151.1 ; off-sheet AM26x_ADC2_AIN5
AM26x_ADC_CAL0: R152.1 ; off-sheet AM26x_ADC_CAL0
HSEC_ADC0_AIN0/DAC_OUT: C79.2 R134.2 U3.1(IO1) ; off-sheet HSEC_ADC0_AIN0/DAC_OUT
HSEC_ADC0_AIN1: C62.2 R135.2 U3.2(IO2) ; off-sheet HSEC_ADC0_AIN1
HSEC_ADC0_AIN2_P: C80.2 R136.2 U3.5(IO4) ; off-sheet HSEC_ADC0_AIN2_P
HSEC_ADC0_AIN3_N: C63.2 R137.2 U3.4(IO3) ; off-sheet HSEC_ADC0_AIN3_N
HSEC_ADC0_AIN4_P: C81.2 R138.2 U4.2(IO2) ; off-sheet HSEC_ADC0_AIN4_P
HSEC_ADC0_AIN5_N: C64.2 R139.2 U4.1(IO1) ; off-sheet HSEC_ADC0_AIN5_N
HSEC_ADC1_AIN0_P: C82.2 R140.2 U4.4(IO3) ; off-sheet HSEC_ADC1_AIN0_P
HSEC_ADC1_AIN1_N: C65.2 R141.2 U4.5(IO4) ; off-sheet HSEC_ADC1_AIN1_N
HSEC_ADC1_AIN2_P: C83.2 R142.2 U5.1(IO1) ; off-sheet HSEC_ADC1_AIN2_P
HSEC_ADC1_AIN3_N: C66.2 R143.2 U5.2(IO2) ; off-sheet HSEC_ADC1_AIN3_N
HSEC_ADC1_AIN4: C84.2 R144.2 U6.1(IO1) ; off-sheet HSEC_ADC1_AIN4
HSEC_ADC1_AIN5: C67.2 R145.2 U6.2(IO2) ; off-sheet HSEC_ADC1_AIN5
HSEC_ADC2_AIN0_P: C85.2 R146.2 U6.5(IO4) ; off-sheet HSEC_ADC2_AIN0_P
HSEC_ADC2_AIN1_N: C68.2 R147.2 U6.4(IO3) ; off-sheet HSEC_ADC2_AIN1_N
HSEC_ADC2_AIN2_P: C86.2 R148.2 U5.5(IO4) ; off-sheet HSEC_ADC2_AIN2_P
HSEC_ADC2_AIN3_N: C69.2 R149.2 U5.4(IO3) ; off-sheet HSEC_ADC2_AIN3_N
HSEC_ADC2_AIN4: C87.2 R150.2 U7.1(IO1) ; off-sheet HSEC_ADC2_AIN4
HSEC_ADC2_AIN5: C70.2 R151.2 U7.2(IO2) ; off-sheet HSEC_ADC2_AIN5
HSEC_ADC_CAL0: C94.2 R152.2 U7.4(IO3) ; off-sheet HSEC_ADC_CAL0

Not connected (* = marked no-connect by the designer): U7 5(IO4)*

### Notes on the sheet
- ADC FILTER
- ESD DIODES
- (near C79) Layout Note: Place RC filters with minimal distance between components

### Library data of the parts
C32-C36 = CMP-0006659-2: as C3 on sheet PROC200_MII0_PHY2
C62-C70 C79-C87 C94 = CMP-0006456-2: CAP, CERM, 330 pF, 50 V, +/- 5%, C0G/NP0, 0402; Manufacturer: MuRata; TaMin_C: -55°C; Polarized: N; SizeAreaWB_mm2: 3; Value1: Unknown; U/M: EA; Value: 330pF; TaMax_C: 125°C; SizeZ_mm: 0.6; SizeX_mm: 1; SizeY_mm: 0.5; Value2: 50V; AEC Category: Q200
R134-R152 = CMP-0026992-3: as R1 on sheet PROC200_MII0_PHY2
U3-U7 = CMP-0043110-1: Low-Capacitance + / - 15-kV ESD Protection Array for High-Speed Data Interfaces, 4 Channels, -40 to +85 degC, 6-pin USON (DPK), Green (RoHS & no Sb/Br); Manufacturer: Texas Instruments; IO Capacitance(Typ)(pF): 1.5; IEC 61000-4-2 Contact(+/- kV): 8; SubFamily: ESD Solution; Breakdown Voltage(Min)(V): 11; 1394 / Firewire: TRUE; IEC 61000-4-2 Air-Gap(+/- kV): 15

## Sheet PROC200_180pin_Edge_Connector.SchDoc
size 431 x 279 mm; SheetNumber: 17; SheetTotal: 18
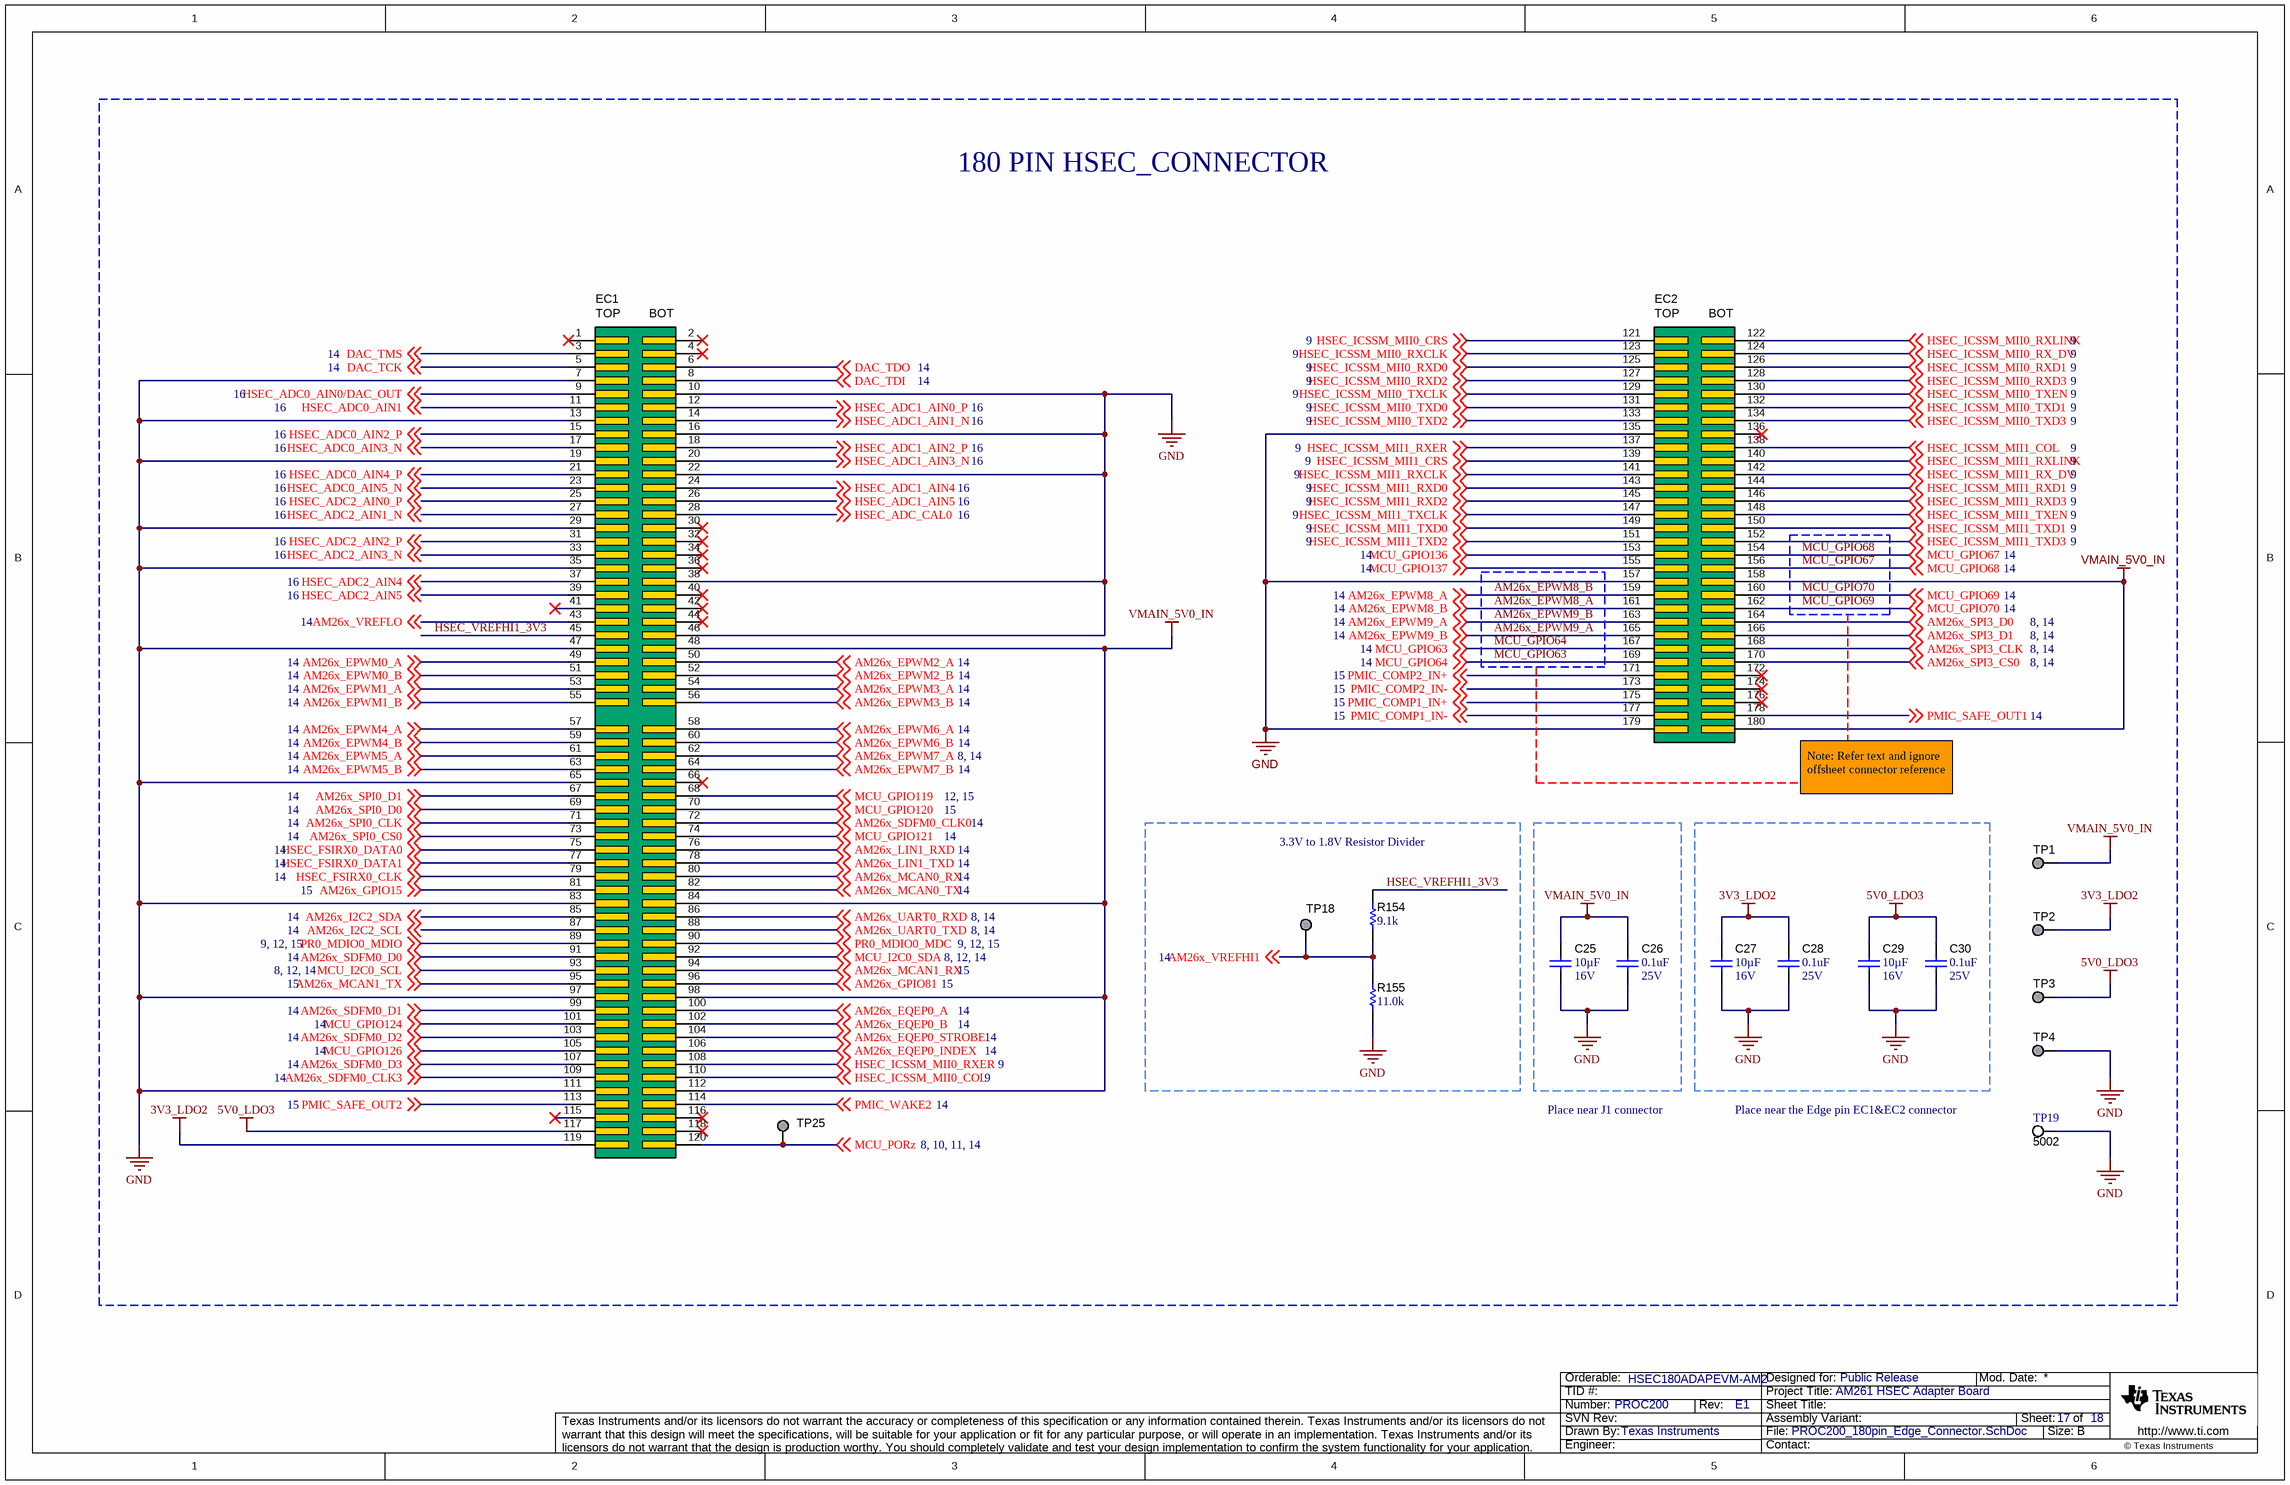
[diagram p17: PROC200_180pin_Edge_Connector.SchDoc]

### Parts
C25  VDC_V: 16V  ValueDisplayed: 10µF  [0603]  (hidden comment: GRM188C81C106MA73D)
C26  VDC_V: 25V  ValueDisplayed: 0.1uF  [0402]  (hidden comment: GRM155R71E104KE14D)
C27  VDC_V: 16V  ValueDisplayed: 10µF  [0603]  (hidden comment: GRM188C81C106MA73D)
C28  VDC_V: 25V  ValueDisplayed: 0.1uF  [0402]  (hidden comment: GRM155R71E104KE14D)
C29  VDC_V: 16V  ValueDisplayed: 10µF  [0603]  (hidden comment: GRM188C81C106MA73D)
C30  VDC_V: 25V  ValueDisplayed: 0.1uF  [0402]  (hidden comment: GRM155R71E104KE14D)
EC1  controlCARD-120HSEC_Edge  [controlCARD-120HSEC_Edge]  (value not drawn)  (no BOM)
EC2  controlCARD-180HSEC-60pinAddon_Edge  [controlCARD-180HSEC-60pinAddon_Edge]  (value not drawn)  (no BOM)
R154  ValueDisplayed: 9.1k  [0402]  (hidden comment: CRCW04029K10JNED)
R155  ValueDisplayed: 11.0k  [0402]  (hidden comment: CRCW040211K0FKED)
TP1  CMP-0078143-4  [TP_25MIL-SMT]  (value not drawn)  (no BOM)
TP2  CMP-0078143-4  [TP_25MIL-SMT]  (value not drawn)  (no BOM)
TP3  CMP-0078143-4  [TP_25MIL-SMT]  (value not drawn)  (no BOM)
TP4  CMP-0078143-4  [TP_25MIL-SMT]  (value not drawn)  (no BOM)
TP18  CMP-0078143-4  [TP_25MIL-SMT]  (value not drawn)  (no BOM)
TP19  5002  [Keystone5002]
TP25  CMP-0078143-4  [TP_25MIL-SMT]  (value not drawn)  (no BOM)

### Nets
3V3_LDO2: C27.2 C28.1 EC1.119 TP2.1
5V0_LDO3: C29.2 C30.1 EC1.117 TP3.1
GND: C25.1 C26.2 C27.1 C28.2 C29.1 C30.2 EC1.7 EC1.10 EC1.13 EC1.16 EC1.19 EC1.22 EC1.29 EC1.35 EC1.38 EC1.46 EC1.47 EC1.65 EC1.83 EC1.97 EC1.111 EC2.135 EC2.157 EC2.179 R155.2 TP4.1 TP19.1
VMAIN_5V0_IN: C25.2 C26.1 EC1.48 EC1.84 EC1.98 EC1.112 EC2.158 EC2.180 TP1.1
AM26x_EPWM0_A: EC1.49 ; off-sheet AM26x_EPWM0_A
AM26x_EPWM0_B: EC1.51 ; off-sheet AM26x_EPWM0_B
AM26x_EPWM1_A: EC1.53 ; off-sheet AM26x_EPWM1_A
AM26x_EPWM1_B: EC1.55 ; off-sheet AM26x_EPWM1_B
AM26x_EPWM2_A: EC1.50 ; off-sheet AM26x_EPWM2_A
AM26x_EPWM2_B: EC1.52 ; off-sheet AM26x_EPWM2_B
AM26x_EPWM3_A: EC1.54 ; off-sheet AM26x_EPWM3_A
AM26x_EPWM3_B: EC1.56 ; off-sheet AM26x_EPWM3_B
AM26x_EPWM4_A: EC1.57 ; off-sheet AM26x_EPWM4_A
AM26x_EPWM4_B: EC1.59 ; off-sheet AM26x_EPWM4_B
AM26x_EPWM5_A: EC1.61 ; off-sheet AM26x_EPWM5_A
AM26x_EPWM5_B: EC1.63 ; off-sheet AM26x_EPWM5_B
AM26x_EPWM6_A: EC1.58 ; off-sheet AM26x_EPWM6_A
AM26x_EPWM6_B: EC1.60 ; off-sheet AM26x_EPWM6_B
AM26x_EPWM7_A: EC1.62 ; off-sheet AM26x_EPWM7_A
AM26x_EPWM7_B: EC1.64 ; off-sheet AM26x_EPWM7_B
AM26x_EPWM8_A: EC2.159 ; off-sheet AM26x_EPWM8_A
AM26x_EPWM8_B: EC2.161 ; off-sheet AM26x_EPWM8_B
AM26x_EPWM9_A: EC2.163 ; off-sheet AM26x_EPWM9_A
AM26x_EPWM9_B: EC2.165 ; off-sheet AM26x_EPWM9_B
AM26x_EQEP0_A: EC1.100 ; off-sheet AM26x_EQEP0_A
AM26x_EQEP0_B: EC1.102 ; off-sheet AM26x_EQEP0_B
AM26x_EQEP0_INDEX: EC1.106 ; off-sheet AM26x_EQEP0_INDEX
AM26x_EQEP0_STROBE: EC1.104 ; off-sheet AM26x_EQEP0_STROBE
AM26x_GPIO15: EC1.81 ; off-sheet AM26x_GPIO15
AM26x_GPIO81: EC1.96 ; off-sheet AM26x_GPIO81
AM26x_I2C2_SCL: EC1.87 ; off-sheet AM26x_I2C2_SCL
AM26x_I2C2_SDA: EC1.85 ; off-sheet AM26x_I2C2_SDA
AM26x_LIN1_RXD: EC1.76 ; off-sheet AM26x_LIN1_RXD
AM26x_LIN1_TXD: EC1.78 ; off-sheet AM26x_LIN1_TXD
AM26x_MCAN0_RX: EC1.80 ; off-sheet AM26x_MCAN0_RX
AM26x_MCAN0_TX: EC1.82 ; off-sheet AM26x_MCAN0_TX
AM26x_MCAN1_RX: EC1.94 ; off-sheet AM26x_MCAN1_RX
AM26x_MCAN1_TX: EC1.95 ; off-sheet AM26x_MCAN1_TX
AM26x_SDFM0_CLK0: EC1.72 ; off-sheet AM26x_SDFM0_CLK0
AM26x_SDFM0_CLK3: EC1.109 ; off-sheet AM26x_SDFM0_CLK3
AM26x_SDFM0_D0: EC1.91 ; off-sheet AM26x_SDFM0_D0
AM26x_SDFM0_D1: EC1.99 ; off-sheet AM26x_SDFM0_D1
AM26x_SDFM0_D2: EC1.103 ; off-sheet AM26x_SDFM0_D2
AM26x_SDFM0_D3: EC1.107 ; off-sheet AM26x_SDFM0_D3
AM26x_SPI0_CLK: EC1.71 ; off-sheet AM26x_SPI0_CLK
AM26x_SPI0_CS0: EC1.73 ; off-sheet AM26x_SPI0_CS0
AM26x_SPI0_D0: EC1.69 ; off-sheet AM26x_SPI0_D0
AM26x_SPI0_D1: EC1.67 ; off-sheet AM26x_SPI0_D1
AM26x_SPI3_CLK: EC2.168 ; off-sheet AM26x_SPI3_CLK
AM26x_SPI3_CS0: EC2.170 ; off-sheet AM26x_SPI3_CS0
AM26x_SPI3_D0: EC2.164 ; off-sheet AM26x_SPI3_D0
AM26x_SPI3_D1: EC2.166 ; off-sheet AM26x_SPI3_D1
AM26x_UART0_RXD: EC1.86 ; off-sheet AM26x_UART0_RXD
AM26x_UART0_TXD: EC1.88 ; off-sheet AM26x_UART0_TXD
AM26x_VREFHI1: R154.2 R155.1 TP18.1 ; off-sheet AM26x_VREFHI1
AM26x_VREFLO: EC1.43 ; off-sheet AM26x_VREFLO
DAC_TCK: EC1.5 ; off-sheet DAC_TCK
DAC_TDI: EC1.8 ; off-sheet DAC_TDI
DAC_TDO: EC1.6 ; off-sheet DAC_TDO
DAC_TMS: EC1.3 ; off-sheet DAC_TMS
HSEC_ADC0_AIN0/DAC_OUT: EC1.9 ; off-sheet HSEC_ADC0_AIN0/DAC_OUT
HSEC_ADC0_AIN1: EC1.11 ; off-sheet HSEC_ADC0_AIN1
HSEC_ADC0_AIN2_P: EC1.15 ; off-sheet HSEC_ADC0_AIN2_P
HSEC_ADC0_AIN3_N: EC1.17 ; off-sheet HSEC_ADC0_AIN3_N
HSEC_ADC0_AIN4_P: EC1.21 ; off-sheet HSEC_ADC0_AIN4_P
HSEC_ADC0_AIN5_N: EC1.23 ; off-sheet HSEC_ADC0_AIN5_N
HSEC_ADC1_AIN0_P: EC1.12 ; off-sheet HSEC_ADC1_AIN0_P
HSEC_ADC1_AIN1_N: EC1.14 ; off-sheet HSEC_ADC1_AIN1_N
HSEC_ADC1_AIN2_P: EC1.18 ; off-sheet HSEC_ADC1_AIN2_P
HSEC_ADC1_AIN3_N: EC1.20 ; off-sheet HSEC_ADC1_AIN3_N
HSEC_ADC1_AIN4: EC1.24 ; off-sheet HSEC_ADC1_AIN4
HSEC_ADC1_AIN5: EC1.26 ; off-sheet HSEC_ADC1_AIN5
HSEC_ADC2_AIN0_P: EC1.25 ; off-sheet HSEC_ADC2_AIN0_P
HSEC_ADC2_AIN1_N: EC1.27 ; off-sheet HSEC_ADC2_AIN1_N
HSEC_ADC2_AIN2_P: EC1.31 ; off-sheet HSEC_ADC2_AIN2_P
HSEC_ADC2_AIN3_N: EC1.33 ; off-sheet HSEC_ADC2_AIN3_N
HSEC_ADC2_AIN4: EC1.37 ; off-sheet HSEC_ADC2_AIN4
HSEC_ADC2_AIN5: EC1.39 ; off-sheet HSEC_ADC2_AIN5
HSEC_ADC_CAL0: EC1.28 ; off-sheet HSEC_ADC_CAL0
HSEC_FSIRX0_CLK: EC1.79 ; off-sheet HSEC_FSIRX0_CLK
HSEC_FSIRX0_DATA0: EC1.75 ; off-sheet HSEC_FSIRX0_DATA0
HSEC_FSIRX0_DATA1: EC1.77 ; off-sheet HSEC_FSIRX0_DATA1
HSEC_ICSSM_MII0_COL: EC1.110 ; off-sheet HSEC_ICSSM_MII0_COL
HSEC_ICSSM_MII0_CRS: EC2.121 ; off-sheet HSEC_ICSSM_MII0_CRS
HSEC_ICSSM_MII0_RX_DV: EC2.124 ; off-sheet HSEC_ICSSM_MII0_RX_DV
HSEC_ICSSM_MII0_RXCLK: EC2.123 ; off-sheet HSEC_ICSSM_MII0_RXCLK
HSEC_ICSSM_MII0_RXD0: EC2.125 ; off-sheet HSEC_ICSSM_MII0_RXD0
HSEC_ICSSM_MII0_RXD1: EC2.126 ; off-sheet HSEC_ICSSM_MII0_RXD1
HSEC_ICSSM_MII0_RXD2: EC2.127 ; off-sheet HSEC_ICSSM_MII0_RXD2
HSEC_ICSSM_MII0_RXD3: EC2.128 ; off-sheet HSEC_ICSSM_MII0_RXD3
HSEC_ICSSM_MII0_RXER: EC1.108 ; off-sheet HSEC_ICSSM_MII0_RXER
HSEC_ICSSM_MII0_RXLINK: EC2.122 ; off-sheet HSEC_ICSSM_MII0_RXLINK
HSEC_ICSSM_MII0_TXCLK: EC2.129 ; off-sheet HSEC_ICSSM_MII0_TXCLK
HSEC_ICSSM_MII0_TXD0: EC2.131 ; off-sheet HSEC_ICSSM_MII0_TXD0
HSEC_ICSSM_MII0_TXD1: EC2.132 ; off-sheet HSEC_ICSSM_MII0_TXD1
HSEC_ICSSM_MII0_TXD2: EC2.133 ; off-sheet HSEC_ICSSM_MII0_TXD2
HSEC_ICSSM_MII0_TXD3: EC2.134 ; off-sheet HSEC_ICSSM_MII0_TXD3
HSEC_ICSSM_MII0_TXEN: EC2.130 ; off-sheet HSEC_ICSSM_MII0_TXEN
HSEC_ICSSM_MII1_COL: EC2.138 ; off-sheet HSEC_ICSSM_MII1_COL
HSEC_ICSSM_MII1_CRS: EC2.139 ; off-sheet HSEC_ICSSM_MII1_CRS
HSEC_ICSSM_MII1_RX_DV: EC2.142 ; off-sheet HSEC_ICSSM_MII1_RX_DV
HSEC_ICSSM_MII1_RXCLK: EC2.141 ; off-sheet HSEC_ICSSM_MII1_RXCLK
HSEC_ICSSM_MII1_RXD0: EC2.143 ; off-sheet HSEC_ICSSM_MII1_RXD0
HSEC_ICSSM_MII1_RXD1: EC2.144 ; off-sheet HSEC_ICSSM_MII1_RXD1
HSEC_ICSSM_MII1_RXD2: EC2.145 ; off-sheet HSEC_ICSSM_MII1_RXD2
HSEC_ICSSM_MII1_RXD3: EC2.146 ; off-sheet HSEC_ICSSM_MII1_RXD3
HSEC_ICSSM_MII1_RXER: EC2.137 ; off-sheet HSEC_ICSSM_MII1_RXER
HSEC_ICSSM_MII1_RXLINK: EC2.140 ; off-sheet HSEC_ICSSM_MII1_RXLINK
HSEC_ICSSM_MII1_TXCLK: EC2.147 ; off-sheet HSEC_ICSSM_MII1_TXCLK
HSEC_ICSSM_MII1_TXD0: EC2.149 ; off-sheet HSEC_ICSSM_MII1_TXD0
HSEC_ICSSM_MII1_TXD1: EC2.150 ; off-sheet HSEC_ICSSM_MII1_TXD1
HSEC_ICSSM_MII1_TXD2: EC2.151 ; off-sheet HSEC_ICSSM_MII1_TXD2
HSEC_ICSSM_MII1_TXD3: EC2.152 ; off-sheet HSEC_ICSSM_MII1_TXD3
HSEC_ICSSM_MII1_TXEN: EC2.148 ; off-sheet HSEC_ICSSM_MII1_TXEN
HSEC_VREFHI1_3V3: EC1.45 R154.1
MCU_GPIO63: EC2.167 ; off-sheet MCU_GPIO63
MCU_GPIO64: EC2.169 ; off-sheet MCU_GPIO64
MCU_GPIO67: EC2.154 ; off-sheet MCU_GPIO67
MCU_GPIO68: EC2.156 ; off-sheet MCU_GPIO68
MCU_GPIO69: EC2.160 ; off-sheet MCU_GPIO69
MCU_GPIO70: EC2.162 ; off-sheet MCU_GPIO70
MCU_GPIO119: EC1.68 ; off-sheet MCU_GPIO119  [project net MII1_INTn]
MCU_GPIO120: EC1.70 ; off-sheet MCU_GPIO120
MCU_GPIO121: EC1.74 ; off-sheet MCU_GPIO121
MCU_GPIO124: EC1.101 ; off-sheet MCU_GPIO124
MCU_GPIO126: EC1.105 ; off-sheet MCU_GPIO126
MCU_GPIO136: EC2.153 ; off-sheet MCU_GPIO136
MCU_GPIO137: EC2.155 ; off-sheet MCU_GPIO137
MCU_I2C0_SCL: EC1.93 ; off-sheet MCU_I2C0_SCL
MCU_I2C0_SDA: EC1.92 ; off-sheet MCU_I2C0_SDA
MCU_PORz: EC1.120 TP25.1 ; off-sheet MCU_PORz
PMIC_COMP1_IN+: EC2.175 ; off-sheet PMIC_COMP1_IN+
PMIC_COMP1_IN-: EC2.177 ; off-sheet PMIC_COMP1_IN-
PMIC_COMP2_IN+: EC2.171 ; off-sheet PMIC_COMP2_IN+
PMIC_COMP2_IN-: EC2.173 ; off-sheet PMIC_COMP2_IN-
PMIC_SAFE_OUT1: EC2.178 ; off-sheet PMIC_SAFE_OUT1
PMIC_SAFE_OUT2: EC1.113 ; off-sheet PMIC_SAFE_OUT2
PMIC_WAKE2: EC1.114 ; off-sheet PMIC_WAKE2
PR0_MDIO0_MDC: EC1.90 ; off-sheet PR0_MDIO0_MDC
PR0_MDIO0_MDIO: EC1.89 ; off-sheet PR0_MDIO0_MDIO

Not connected (* = marked no-connect by the designer): EC1 1* 2* 4* 30* 32* 34* 36* 40* 41* 42* 44* 66* 115* 116* 118*; EC2 136* 172* 174* 176*

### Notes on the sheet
- 180 PIN HSEC_CONNECTOR
- MCU_GPIO67
- MCU_GPIO68
- AM26x_EPWM9_B
- AM26x_EPWM9_A
- AM26x_EPWM8_B
- AM26x_EPWM8_A
- MCU_GPIO69
- MCU_GPIO70
- MCU_GPIO64
- MCU_GPIO63
- Note: Refer text and ignore offsheet connector reference
- 3.3V to 1.8V Resistor Divider
- Place near J1 connector
- Place near the Edge pin EC1&EC2 connector

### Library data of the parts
C25 C27 C29 = CMP-0086062-1: as C1 on sheet PROC200_MII0_PHY2
C26 C28 C30 = CMP-0006659-2: as C3 on sheet PROC200_MII0_PHY2
EC1 = CMP-0003813-3: C2000 controlCARD-120HSEC Edge Connector for Samtec HSEC8-160-01-L-DV-A-BL; Manufacturer: Any; Note: The pin numbering does not match Samtec datasheet
EC2 = CMP-0081961-1: C2000 controlCARD-180HSEC (60-pin addon) Edge connector for Samtec HSEC8-130-01-L-DV-A; Manufacturer: Any; Note: The pin numbering does not match Samtec datasheet
R154 = CMP-0026989-6: RES, 9.1 k, 5%, 0.063 W, AEC-Q200 Grade 0, 0402; Manufacturer: Vishay-Dale; Value: 9.1k; AEC Category: Q200; Value_Code: 9k10; SizeArea_mm2: 0.5; SizeX_mm: 1; Value2: 0.063W; EIA_Code: E24; TempCo: 200 ppm/C; VDC_V: 50V; SizeZ_mm: 0.6; AEC Grade: 0; AEC Qualified: Y; Power_W: 63mW
R155 = CMP-0025975-3: as R2 on sheet PROC200_MII0_PHY2
TP1-TP4 TP18 TP25 = CMP-0078143-4: TEST POINT.  No entry in BOM.
TP19 = CMP-0055139-2: Test Point, Miniature, White, TH; Manufacturer: Keystone Electronics; ContactFinish: Silver; Green_REACh: Passed; CT: TRUE; Green_Lifecycle: Active; CNHeader: FALSE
